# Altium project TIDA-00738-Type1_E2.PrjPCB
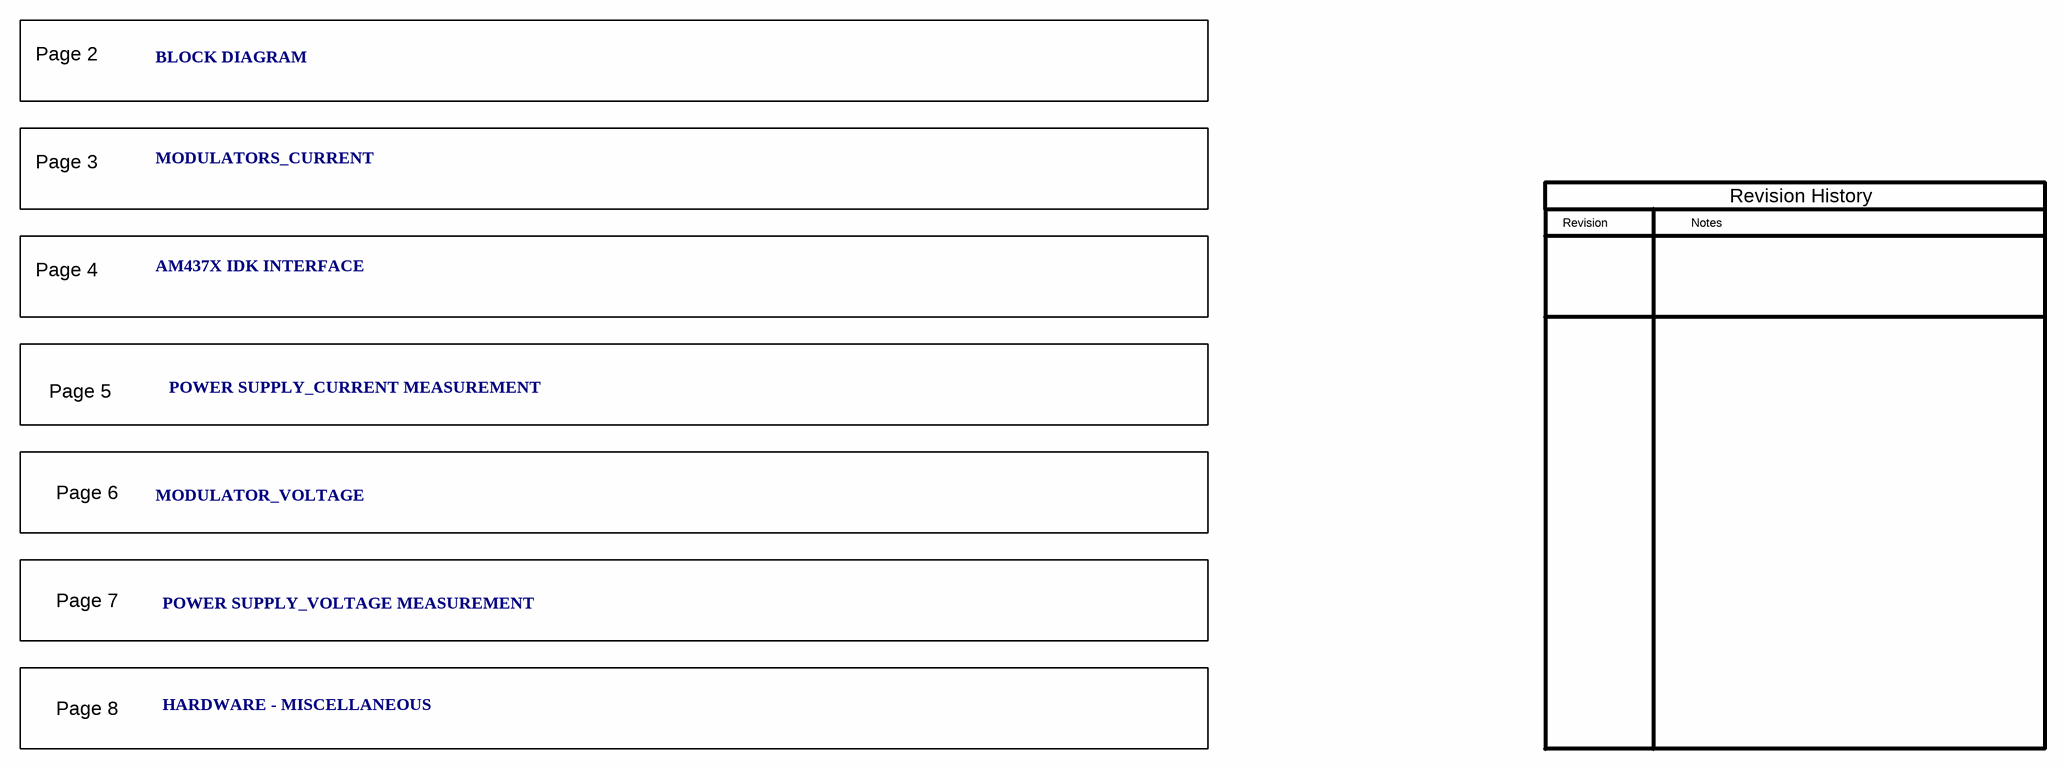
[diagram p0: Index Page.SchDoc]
CopyrightYear: 2013; PCB_Layout: Avinash; PCB_Rev: E2; PRJ_Customer: Public Release; PRJ_Engineer: Sunil Dwivedi; PRJ_Number: TIDA-00738; PRJ_Title: ICVM Using AMC1304 and SITARA Controller; SCH_Rev: E2; TechSupport: http://www.ti.com/support
8 sheets, 252 parts. Net scope: flat (ports and power ports of the same name join across sheets).
Board file: TIDA-00738-Type1_E2.PcbDoc
Sheets:
  Index Page.SchDoc
  Cover Sheet_ANSI-B.SchDoc
  Current Measurement.SchDoc
  Clock Generator.SchDoc
  Power Supply Current Measurment.SchDoc
  Voltage Measurment.SchDoc
  Power Supply Voltage Measurement.SchDoc
  Hardware_ANSI-B.SchDoc

## Sheet Index Page.SchDoc
size 431 x 279 mm; Date: Not shown in title block; ApprovedBy: Not shown in title block; CheckedBy: Not shown in title block; Author: Not shown in title block; CompanyName: Not shown in title block; Engineer: Not shown in title block; Organization: Not shown in title block; Address1: Not shown in title block; Address2: Not shown in title block; Address3: Not shown in title block; Address4: Not shown in title block; DocumentNumber: 1; Revision: Use project parameter SCH_Rev; SheetNumber: 1; SheetTotal: 8; PageSetup: Record=PageOptions¦CenterHorizontal=True¦CenterVertical=True¦PrintScale=1.00¦XCorrection=1.00¦YCorrection=1.00¦PrintKind=0¦BorderSize=5000000¦LeftOffset=0¦BottomOffset=0¦Orientation=2¦PaperLength=1000¦PaperWidth=1000¦Scale=100¦PaperSource=15¦PrintQuality=600¦MediaType=1¦DitherType=10¦PaperKind=Letter¦PrintScaleMode=1

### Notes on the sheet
- Page 2
- BLOCK DIAGRAM
- Page 3
- MODULATORS_CURRENT
- Revision
- Notes
- Revision History
- Page 4
- AM437X IDK INTERFACE
- Page 5
- POWER SUPPLY_CURRENT MEASUREMENT
- Page 6
- MODULATOR_VOLTAGE
- Page 7
- POWER SUPPLY_VOLTAGE MEASUREMENT
- Page 8
- HARDWARE - MISCELLANEOUS

## Sheet Cover Sheet_ANSI-B.SchDoc: Cover Sheet
size 431 x 279 mm; Date: Not shown in title block; ApprovedBy: Not shown in title block; CheckedBy: Not shown in title block; Author: Not shown in title block; CompanyName: Not shown in title block; Engineer: Not shown in title block; Organization: Not shown in title block; Address1: Not shown in title block; Address2: Not shown in title block; Address3: Not shown in title block; Address4: Not shown in title block; DocumentNumber: 1; Revision: Use project parameter SCH_Rev; SheetNumber: 2; SheetTotal: 8; PageSetup: Record=PageOptions¦CenterHorizontal=True¦CenterVertical=True¦PrintScale=1.00¦XCorrection=1.00¦YCorrection=1.00¦PrintKind=0¦BorderSize=5000000¦LeftOffset=0¦BottomOffset=0¦Orientation=2¦PaperLength=1000¦PaperWidth=1000¦Scale=100¦PaperSource=15¦PrintQuality=600¦MediaType=1¦DitherType=10¦PaperKind=Letter¦PrintScaleMode=1
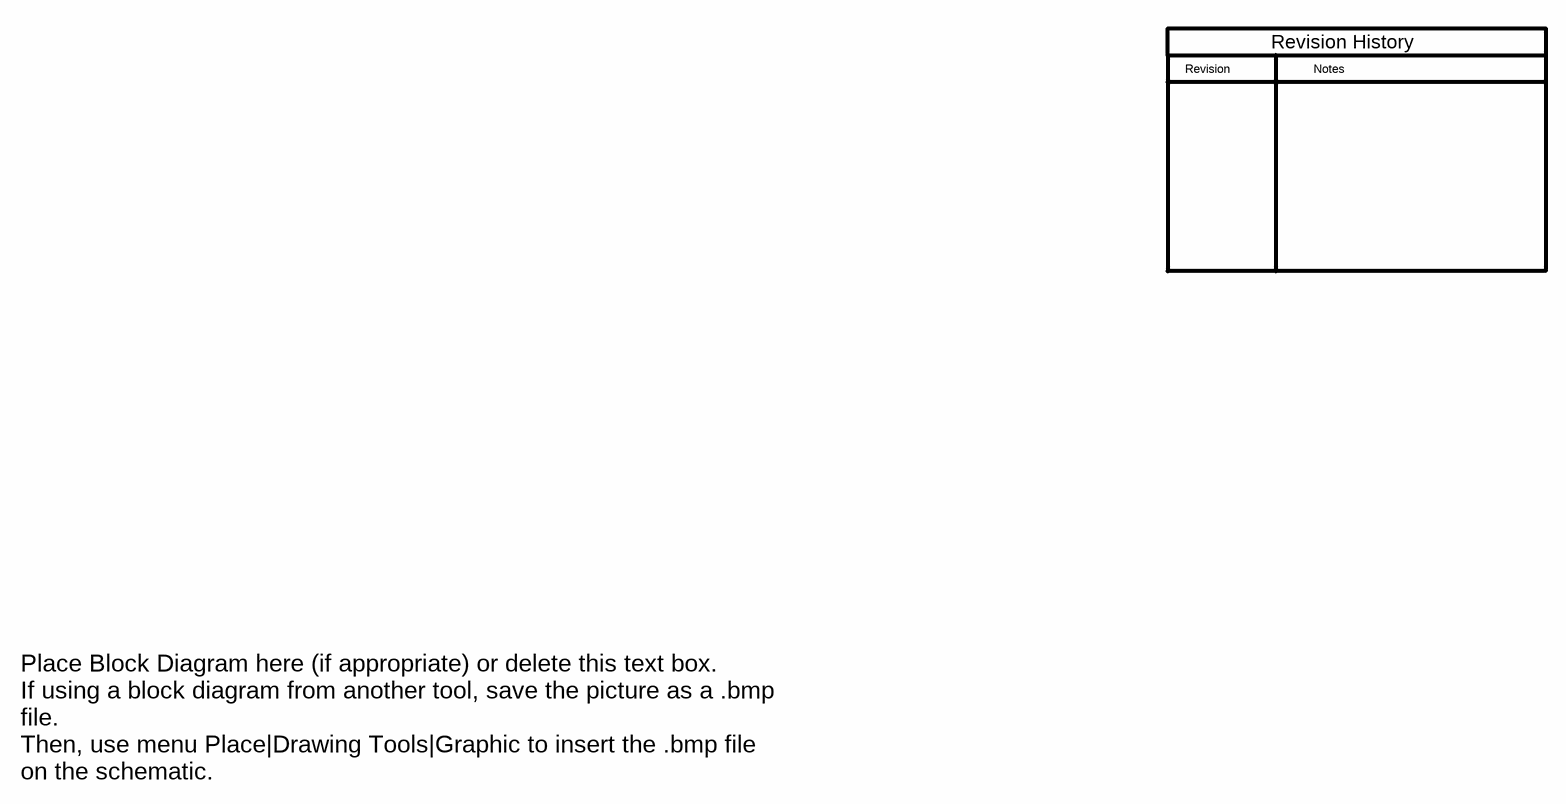
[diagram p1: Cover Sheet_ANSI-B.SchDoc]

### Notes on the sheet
- Revision
- Notes
- Revision History
- Place Block Diagram here (if appropriate) or delete this text box.
  If using a block diagram from another tool, save the picture as a .bmp file.
  Then, use menu Place|Drawing Tools|Graphic to insert the .bmp file on the schematic.

## Sheet Current Measurement.SchDoc: Current Measurement
size 431 x 279 mm; Date: Not shown in title block; ApprovedBy: Not shown in title block; CheckedBy: Not shown in title block; Author: Not shown in title block; CompanyName: Not shown in title block; Engineer: Not shown in title block; Organization: Not shown in title block; Address1: Not shown in title block; Address2: Not shown in title block; Address3: Not shown in title block; Address4: Not shown in title block; DocumentNumber: 1; Revision: Use project parameter SCH_Rev; SheetNumber: 3; SheetTotal: 8; PageSetup: Record=PageOptions¦CenterHorizontal=True¦CenterVertical=True¦PrintScale=1.00¦XCorrection=1.00¦YCorrection=1.00¦PrintKind=0¦BorderSize=5000000¦LeftOffset=0¦BottomOffset=0¦Orientation=2¦PaperLength=1000¦PaperWidth=1000¦Scale=100¦PaperSource=15¦PrintQuality=600¦MediaType=1¦DitherType=10¦PaperKind=Letter¦PrintScaleMode=1
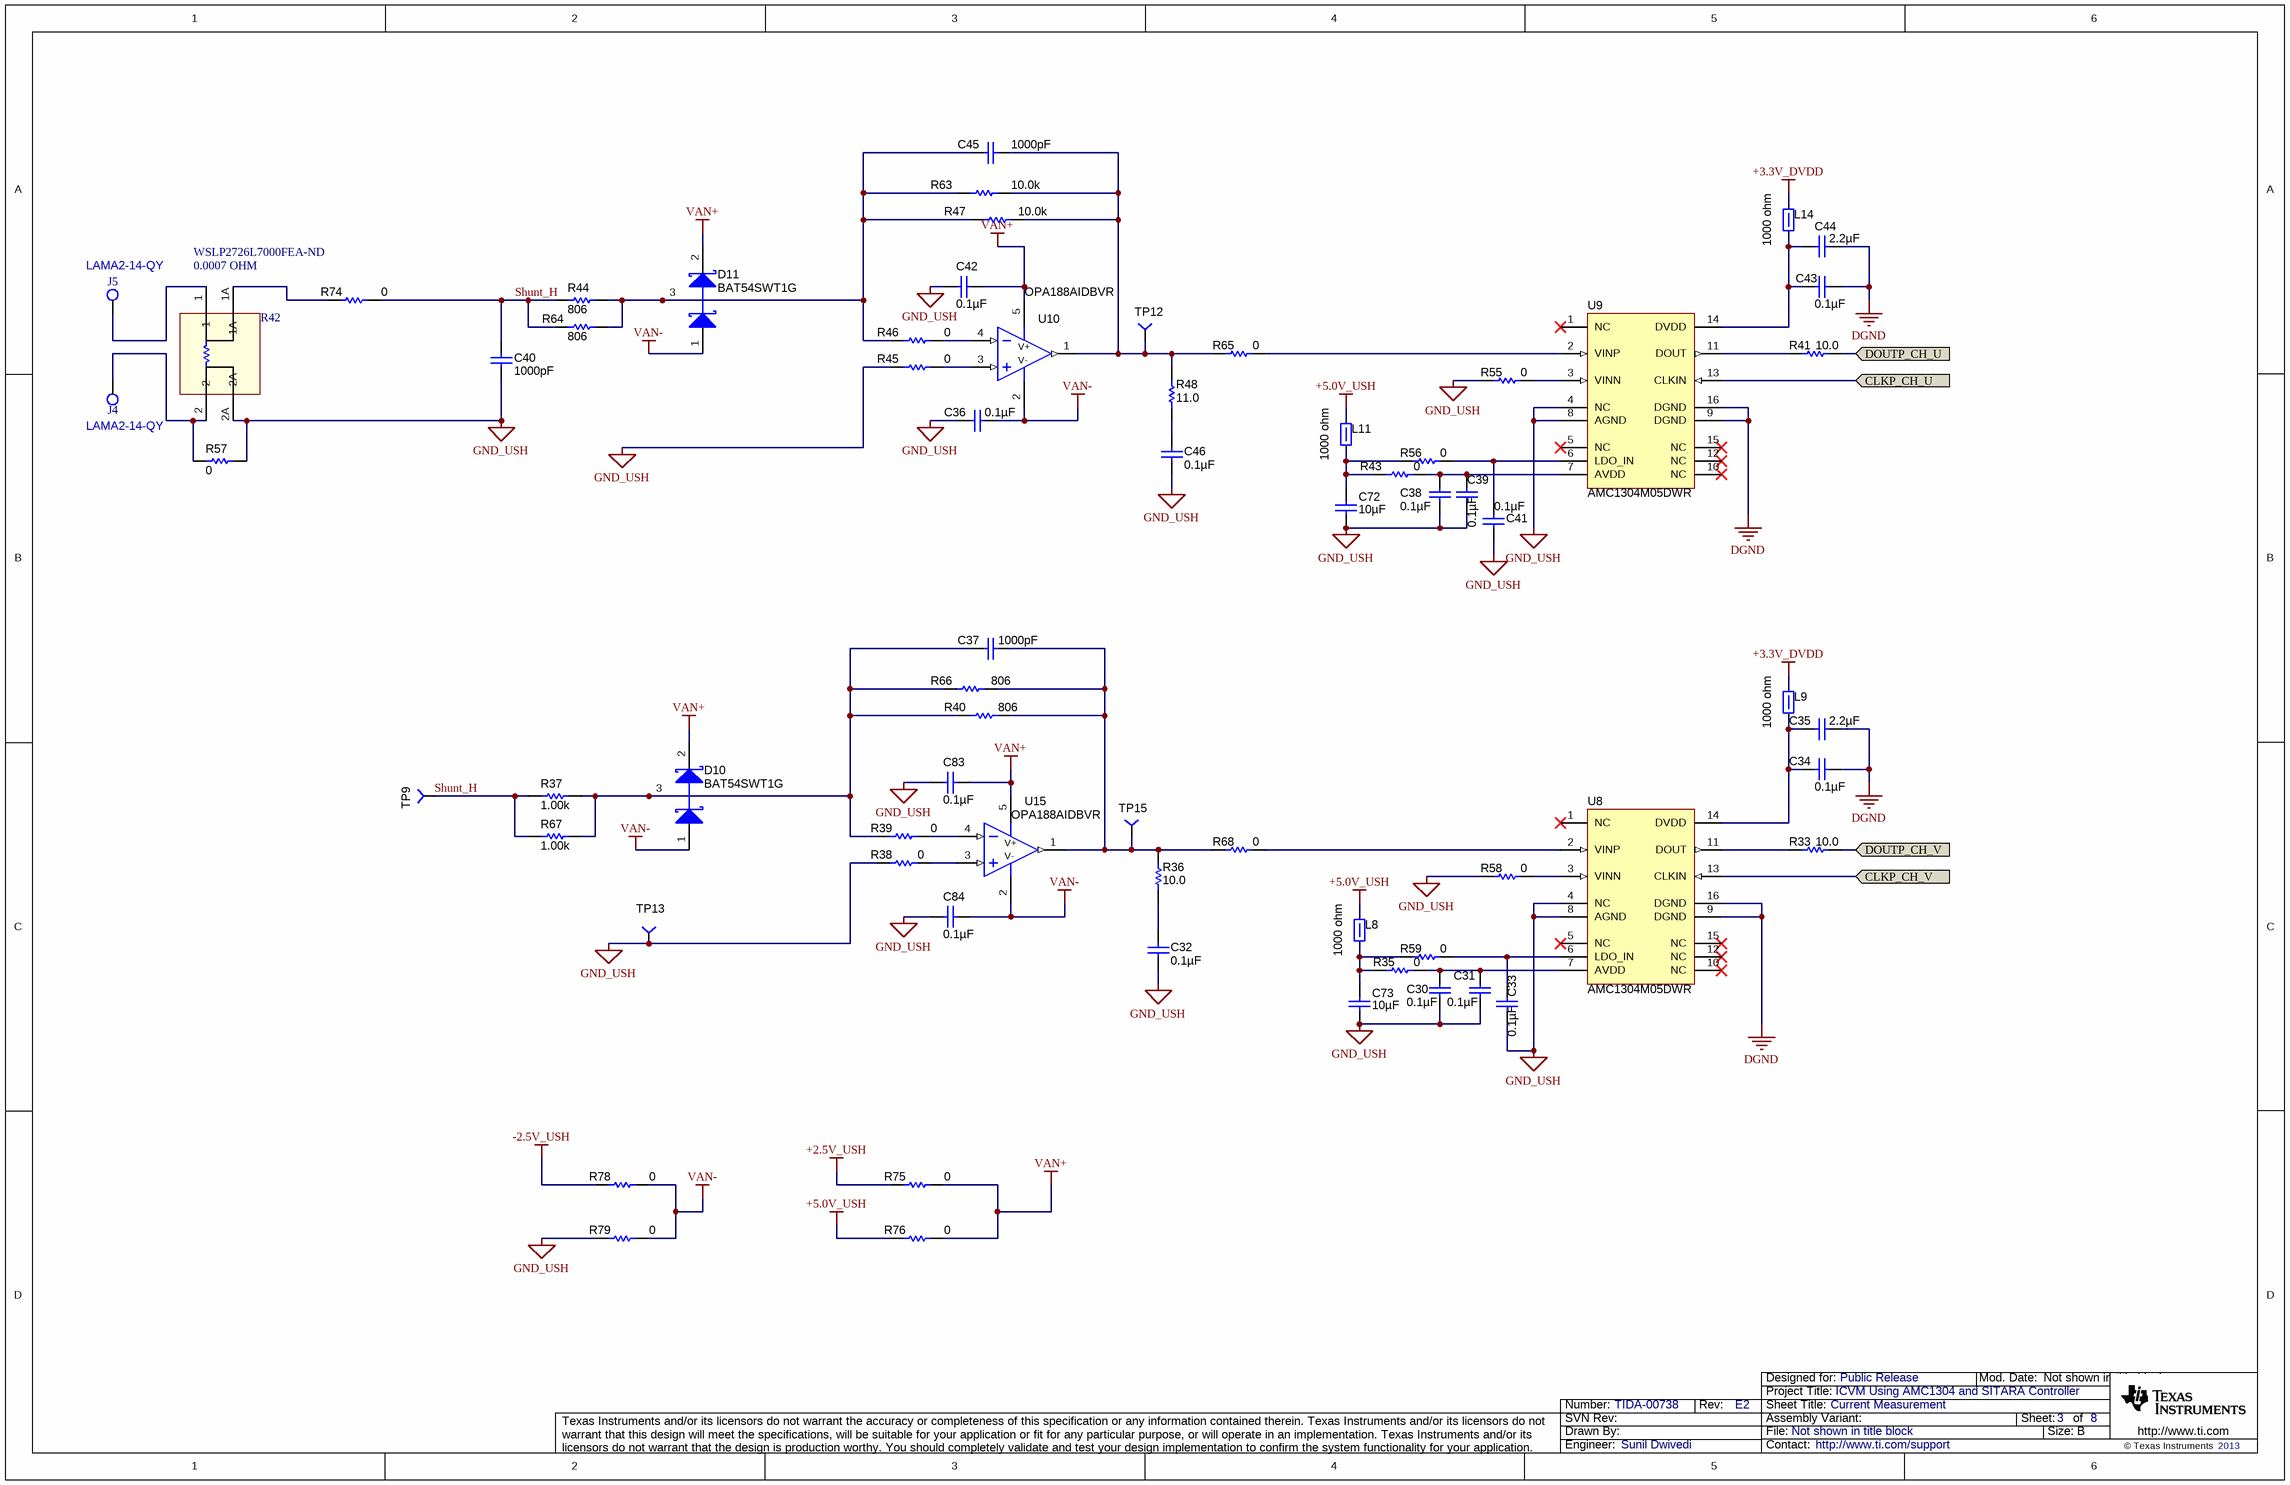
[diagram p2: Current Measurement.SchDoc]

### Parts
C30  ValueDisplayed: 0.1µF  [0603]
C31  ValueDisplayed: 0.1µF  [0603]
C32  ValueDisplayed: 0.1µF  [0603]  (hidden comment: GRM188R72A104KA35D)
C33  ValueDisplayed: 0.1µF  [0603]
C34  ValueDisplayed: 0.1µF  [0603]
C35  ValueDisplayed: 2.2µF  [0603]  (hidden comment: GRM188R71A225KE15D)
C36  ValueDisplayed: 0.1µF  [0603]
C37  ValueDisplayed: 1000pF  [0603]  (hidden comment: GRM1885C1H102FA01J)
C38  ValueDisplayed: 0.1µF  [0603]
C39  ValueDisplayed: 0.1µF  [0603]
C40  ValueDisplayed: 1000pF  [0603]  (hidden comment: GRM1885C1H102FA01J)
C41  ValueDisplayed: 0.1µF  [0603]
C42  ValueDisplayed: 0.1µF  [0603]
C43  ValueDisplayed: 0.1µF  [0603]
C44  ValueDisplayed: 2.2µF  [0603]  (hidden comment: GRM188R71A225KE15D)
C45  ValueDisplayed: 1000pF  [0603]  (hidden comment: GRM1885C1H102FA01J)
C46  ValueDisplayed: 0.1µF  [0603]  (hidden comment: GRM188R72A104KA35D)
C72  ValueDisplayed: 10µF  [1210]
C73  ValueDisplayed: 10µF  [1210]
C83  ValueDisplayed: 0.1µF  [0603]
C84  ValueDisplayed: 0.1µF  [0603]
D10  BAT54SWT1G  [SOT-323]
D11  BAT54SWT1G  [SOT-323]
J4  LAMA2-14-QY  [PANDUIT_LAMA2-14-QY]
J5  LAMA2-14-QY  [PANDUIT_LAMA2-14-QY]
L8  value 1000 ohm  [MMZ1608_095]  (hidden comment: MMZ1608B102CTA00)
L9  value 1000 ohm  [MMZ1608_095]  (hidden comment: MMZ1608B102CTA00)
L11  value 1000 ohm  [MMZ1608_095]  (hidden comment: MMZ1608B102CTA00)
L14  value 1000 ohm  [MMZ1608_095]  (hidden comment: MMZ1608B102CTA00)
R33  value 10.0  [0603]
R35  value 0  [0603]
R36  ValueDisplayed: 10.0  [0603]  (hidden comment: RC0603FR-0710RL)
R37  ValueDisplayed: 1.00k  [0603]  (hidden comment: CRCW06031K00FKEA)
R38  value 0  [0603]
R39  ValueDisplayed: 0  [0603]  (hidden comment: CRCW06030000Z0EA)
R40  ValueDisplayed: 806  [0603]  (hidden comment: CRCW0603806RFKEA)
R41  value 10.0  [0603]
R42  WSLP2726L7000FEA-ND  value 0.0007 OHM  [RES_WSLP2726]
R43  value 0  [0603]
R44  ValueDisplayed: 806  [0603]  (hidden comment: CRCW0603806RFKEA)
R45  value 0  [0603]
R46  ValueDisplayed: 0  [0603]  (hidden comment: CRCW06030000Z0EA)
R47  ValueDisplayed: 10.0k  [0603]  (hidden comment: RC0603FR-0710KL)
R48  ValueDisplayed: 11.0  [0603]  (hidden comment: RC0603FR-0711RL)
R55  value 0  [0603]
R56  value 0  [0603]
R57  ValueDisplayed: 0  [1206]  (hidden comment: CRCW12060000Z0EA)
R58  value 0  [0603]
R59  value 0  [0603]
R63  ValueDisplayed: 10.0k  [0603]  (hidden comment: RC0603FR-0710KL)
R64  ValueDisplayed: 806  [0603]  (hidden comment: CRCW0603806RFKEA)
R65  value 0  [0603]
R66  ValueDisplayed: 806  [0603]  (hidden comment: CRCW0603806RFKEA)
R67  ValueDisplayed: 1.00k  [0603]  (hidden comment: CRCW06031K00FKEA)
R68  value 0  [0603]
R74  value 0  [0603]
R75  value 0  [0603]
R76  value 0  [0603]
R78  value 0  [0603]
R79  value 0  [0603]
TP9  (no value)  [TP-040_RND]
TP12  (no value)  [TP-040_RND]
TP13  (no value)  [TP-040_RND]
TP15  (no value)  [TP-040_RND]
U8  AMC1304M05DWR  [DW0016B_N]
U9  AMC1304M05DWR  [DW0016B_N]
U10  OPA188AIDBVR  [DBV0005A_N]
U15  OPA188AIDBVR  [DBV0005A_N]

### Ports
CLKP_CH_U, CLKP_CH_V, DOUTP_CH_U, DOUTP_CH_V

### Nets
+2.5V_USH: R75.1
+3.3V_DVDD: L9.2 L14.2
+5.0V_USH: L8.2 L11.2 R76.1
-2.5V_USH: R78.1
DGND: C34.1 C35.1 C43.1 C44.1 U8.9(DGND) U8.16(DGND) U9.9(DGND) U9.16(DGND)
GND_USH: C30.2 C31.2 C32.2 C33.2 C36.1 C38.2 C39.2 C40.2 C41.2 C42.1 C46.2 C72.1 C73.1 C83.1 C84.1 R38.1 R42.2A R45.1 R55.1 R57.2 R58.1 R79.1 TP13.1 U8.4(NC) U8.8(AGND) U9.4(NC) U9.8(AGND)
VAN+: C42.2 C83.2 D10.2(K) D11.2(K) R75.2 R76.2 U10.5(V+) U15.5(V+)
VAN-: C36.2 C84.2 D10.1(A) D11.1(A) R78.2 R79.2 U10.2(V-) U15.2(V-)
CLKP_CH_U: U9.13(CLKIN) ; port CLKP_CH_U
CLKP_CH_V: U8.13(CLKIN) ; port CLKP_CH_V
DOUTP_CH_U: R41.2 ; port DOUTP_CH_U
DOUTP_CH_V: R33.2 ; port DOUTP_CH_V
Shunt_H: C40.1 R37.1 R44.1 R64.1 R67.1 R74.2 TP9.1
NetC30_1: C30.1 C31.1 R35.2 U8.7(AVDD)
NetC32_1: C32.1 R36.1
NetC33_1: C33.1 R59.2 U8.6(LDO_IN)
NetC34_2: C34.2 C35.2 L9.1 U8.14(DVDD)
NetC37_1: C37.1 R36.2 R40.2 R66.2 R68.1 TP15.1 U15.1(OUT)
NetC37_2: C37.2 D10.3(C) R37.2 R39.1 R40.1 R66.1 R67.2
NetC38_1: C38.1 C39.1 R43.2 U9.7(AVDD)
NetC41_1: C41.1 R56.2 U9.6(LDO_IN)
NetC43_2: C43.2 C44.2 L14.1 U9.14(DVDD)
NetC45_1: C45.1 R47.2 R48.2 R63.2 R65.1 TP12.1 U10.1(OUT)
NetC45_2: C45.2 D11.3(C) R44.2 R46.1 R47.1 R63.1 R64.2
NetC46_1: C46.1 R48.1
NetC72_2: C72.2 L11.1 R43.1 R56.1
NetC73_2: C73.2 L8.1 R35.1 R59.1
NetJ4_1: J4.1 R42.2 R57.1
NetJ5_1: J5.1 R42.1
NetR33_1: R33.1 U8.11(DOUT)
NetR38_2: R38.2 U15.3(IN+)
NetR39_2: R39.2 U15.4(IN-)
NetR41_1: R41.1 U9.11(DOUT)
NetR42_1A: R42.1A R74.1
NetR45_2: R45.2 U10.3(IN+)
NetR46_2: R46.2 U10.4(IN-)
NetR55_2: R55.2 U9.3(VINN)
NetR58_2: R58.2 U8.3(VINN)
NetR65_2: R65.2 U9.2(VINP)
NetR68_2: R68.2 U8.2(VINP)

Not connected (* = marked no-connect by the designer): U8 1(NC)* 5(NC)* 10(NC)* 12(NC)* 15(NC)*; U9 1(NC)* 5(NC)* 10(NC)* 12(NC)* 15(NC)*

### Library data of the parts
C30 C31 C33 C36 C38 C39 C41 C42 C83 C84 = C0603C104K5RACTU: CAP, CERM, 0.1uF, 50V, +/-10%, X7R, 0603; Manufacturer: Kemet; Polarized: N; CompType: Capacitor; U/M: EA; Cap_F: 0.0000001; Tolerance_%: 10; Value1: Unknown; VDC_V: 50; TaMin_C: -55; TaMax_C: 125
C32 C46 = GRM188R72A104KA35D: CAP, CERM, 0.1 µF, 100 V, +/- 10%, X7R, 0603; Manufacturer: MuRata; Polarized: N; CompType: Capacitor; Value: 0.1uF; U/M: EA; Cap_F: 0.0000001; Tolerance_%: 10; Value1: Unknown; VDC_V: 100; Value2: 100V; TaMin_C: -55; TaMax_C: 125; AEC Category: Q200
C34 C43 = 06033C104JAT2A: CAP, CERM, 0.1uF, 25V, +/-5%, X7R, 0603; Manufacturer: AVX; Polarized: N; CompType: Capacitor; U/M: EA; Cap_F: 0.0000001; Tolerance_%: 5; ESR_Ohm: 0.05; Value1: 0.05 ohm; VDC_V: 25; TaMin_C: -55; TaMax_C: 125
C35 C44 = GRM188R71A225KE15D: CAP, CERM, 2.2 µF, 10 V, +/- 10%, X7R, 0603; Manufacturer: MuRata; Polarized: N; CompType: Capacitor; Value: 2.2uF; U/M: EA; Cap_F: 0.0000022; Tolerance_%: 10; ESR_ohm: 0.009; Value1: 0.009 ohm; Value2: 10V; TaMin_C: -55; TaMax_C: 125; AEC Category: Q200
C37 C40 C45 = GRM1885C1H102FA01J: CAP, CERM, 1000 pF, 50 V, +/- 1%, C0G/NP0, 0603; Manufacturer: MuRata; Polarized: N; CompType: Capacitor; Value: 1000pF; U/M: EA; Cap_F: 0.000000001; Tolerance_%: 1; Value1: Unknown; VDC_V: 50; Value2: 50V; TaMin_C: -55; TaMax_C: 125; AEC Category: Q200
C72 C73 = GMK325AB7106MM-T: CAP, CERM, 10uF, 35V, +/-20%, X7R, 1210; Manufacturer: Taiyo Yuden; Polarized: N; CompType: Capacitor; U/M: EA; Cap_F: 0.00001; Tolerance_%: 20; Value1: Unknown; VDC_V: 35; TaMin_C: -55; TaMax_C: 125
D10 D11 = BAT54SWT1G: Diode, Schottky, 30 V, 0.2 A, SOT-323; Manufacturer: Fairchild Semiconductor; U/M: EA; Vf_V: 0.8; Value: 30V; Value1: 0.2A; Value2: 0.8V; Io_A: 0.2; Vr_V: 30; TJmax_C: 125; AEC Category: Q101
J4 J5 = LAMA2-14-QY: MECHANICAL LUG ALUM 2-14 AWG; Manufacturer: Panduit Corp
L8 L9 L11 L14 = MMZ1608B102CTA00: Ferrite Bead, 1000 ohm @ 100 MHz, 0.3 A, 0603; Manufacturer: TDK; Imax_A: 0.3; DCR_ohm: 0.6; Value1: 0.6 ohm; Value2: 0.3A; ZTyp@100MHz_Ohm: 1000
R33 R41 = CRCW060310R0FKEA: RES, 10.0 ohm, 1%, 0.1W, 0603; Manufacturer: Vishay-Dale; CompType: Resistor; Res_ohm: 10; Value_Code: 10R0; Tolerance_%: 1; Power_W: 0.1; VDC_V: 75; TempCo: 100 ppm/C; EIA_Code: E96; U/M: EA
R35 R38 R43 R45 R55 R56 R58 R59 R65 R68 R74-R76 R78 R79 = CRCW06030000Z0EA: RES, 0 ohm, 5%, 0.1W, 0603; Manufacturer: Vishay-Dale; CompType: Resistor; Value_Code: 0000; Tolerance_%: 5; Power_W: 0.1; VDC_V: 75; TempCo: 200 ppm/C; EIA_Code: E24; U/M: EA
R36 = RC0603FR-0710RL: RES, 10.0, 1%, 0.1 W, 0603; Manufacturer: Yageo America; CompType: Resistor; Value: 10.0; Res_ohm: 10; Value_Code: 10R0; Tolerance_%: 1; Power_W: 0.1; Value2: 0.1W; VDC_V: 150; TempCo: 200 ppm/C; EIA_Code: E96; U/M: EA; AEC Category: Q200
R37 R67 = CRCW06031K00FKEA: RES, 1.00 k, 1%, 0.1 W, 0603; Manufacturer: Vishay-Dale; CompType: Resistor; Value: 1.00k; Res_ohm: 1000; Value_Code: 1k00; Tolerance_%: 1; Power_W: 0.1; Value2: 0.1W; VDC_V: 75; TempCo: 100 ppm/C; EIA_Code: E96; U/M: EA; AEC Category: Q200
R39 R46 = CRCW06030000Z0EA: RES, 0, 5%, 0.1 W, 0603; Manufacturer: Vishay-Dale; CompType: Resistor; Value: 0; Value_Code: 0000; Tolerance_%: 5; Power_W: 0.1; Value2: 0.1W; VDC_V: 75; TempCo: 200 ppm/C; EIA_Code: E24; U/M: EA; AEC Category: Q200
R40 R44 R64 R66 = CRCW0603806RFKEA: RES, 806, 1%, 0.1 W, 0603; Manufacturer: Vishay-Dale; CompType: Resistor; Value: 806; Value_Code: 806R; Tolerance_%: 1; Power_W: 0.1; Value2: 0.1W; VDC_V: 75; TempCo: 100 ppm/C; EIA_Code: E96; U/M: EA; AEC Category: Q200
R42 = WSLP2726L5000FEA: RES SMD 0.0007 OHM 1% 7W 2726; Manufacturer: VISHAY; CompType: RESISTOR; SymbolCreator: x0199378
R47 R63 = RC0603FR-0710KL: RES, 10.0 k, 1%, 0.1 W, 0603; Manufacturer: Yageo America; CompType: Resistor; Value: 10.0k; Res_ohm: 10000; Value_Code: 10k0; Tolerance_%: 1; Power_W: 0.1; Value2: 0.1W; VDC_V: 150; TempCo: 200 ppm/C; EIA_Code: E96; U/M: EA; AEC Category: Q200
R48 = RC0603FR-0711RL: RES, 11.0, 1%, 0.1 W, 0603; Manufacturer: Yageo America; CompType: Resistor; Value: 11.0; Res_ohm: 11; Value_Code: 11R0; Tolerance_%: 1; Power_W: 0.1; Value2: 0.1W; VDC_V: 150; TempCo: 200 ppm/C; EIA_Code: E96; U/M: EA; AEC Category: Q200
R57 = CRCW12060000Z0EA: RES, 0, 5%, 0.25 W, 1206; Manufacturer: Vishay-Dale; CompType: Resistor; Value: 0; Value_Code: 0000; Tolerance_%: 5; Power_W: 0.25; Value2: 0.25W; VDC_V: 200; TempCo: 200 ppm/C; EIA_Code: E24; U/M: EA
TP9 TP12 TP13 TP15 = TP-040_RND: Test Point, O.040 Hole; Manufacturer: STD; Value: STD
U8 U9 = AMC1304M25DW: High-Precision, Reinforced Isolated Delta-Sigma Modulators with LDO, DW0016B; Manufacturer: Texas Instruments; SymbolCreator: a0411947; CompType: IC; U/M: EA
U10 U15 = OPA188AIDBVR: Precision, Low-Noise, Rail-to-Rail Output, 36 V, Zero-Drift Operational Amplifiers, DBV0005A; Alternate PartNumber: OPA188AIDBVT; Manufacturer: Texas Instruments; CompType: IC; U/M: EA

## Sheet Clock Generator.SchDoc: Clock Generator
size 431 x 279 mm; Date: Not shown in title block; ApprovedBy: Not shown in title block; CheckedBy: Not shown in title block; Author: Not shown in title block; CompanyName: Not shown in title block; Engineer: Not shown in title block; Organization: Not shown in title block; Address1: Not shown in title block; Address2: Not shown in title block; Address3: Not shown in title block; Address4: Not shown in title block; DocumentNumber: 1; Revision: Use project parameter SCH_Rev; SheetNumber: 4; SheetTotal: 8; PageSetup: Record=PageOptions¦CenterHorizontal=True¦CenterVertical=True¦PrintScale=1.00¦XCorrection=1.00¦YCorrection=1.00¦PrintKind=0¦BorderSize=5000000¦LeftOffset=0¦BottomOffset=0¦Orientation=2¦PaperLength=1000¦PaperWidth=1000¦Scale=100¦PaperSource=15¦PrintQuality=600¦MediaType=1¦DitherType=10¦PaperKind=Letter¦PrintScaleMode=1
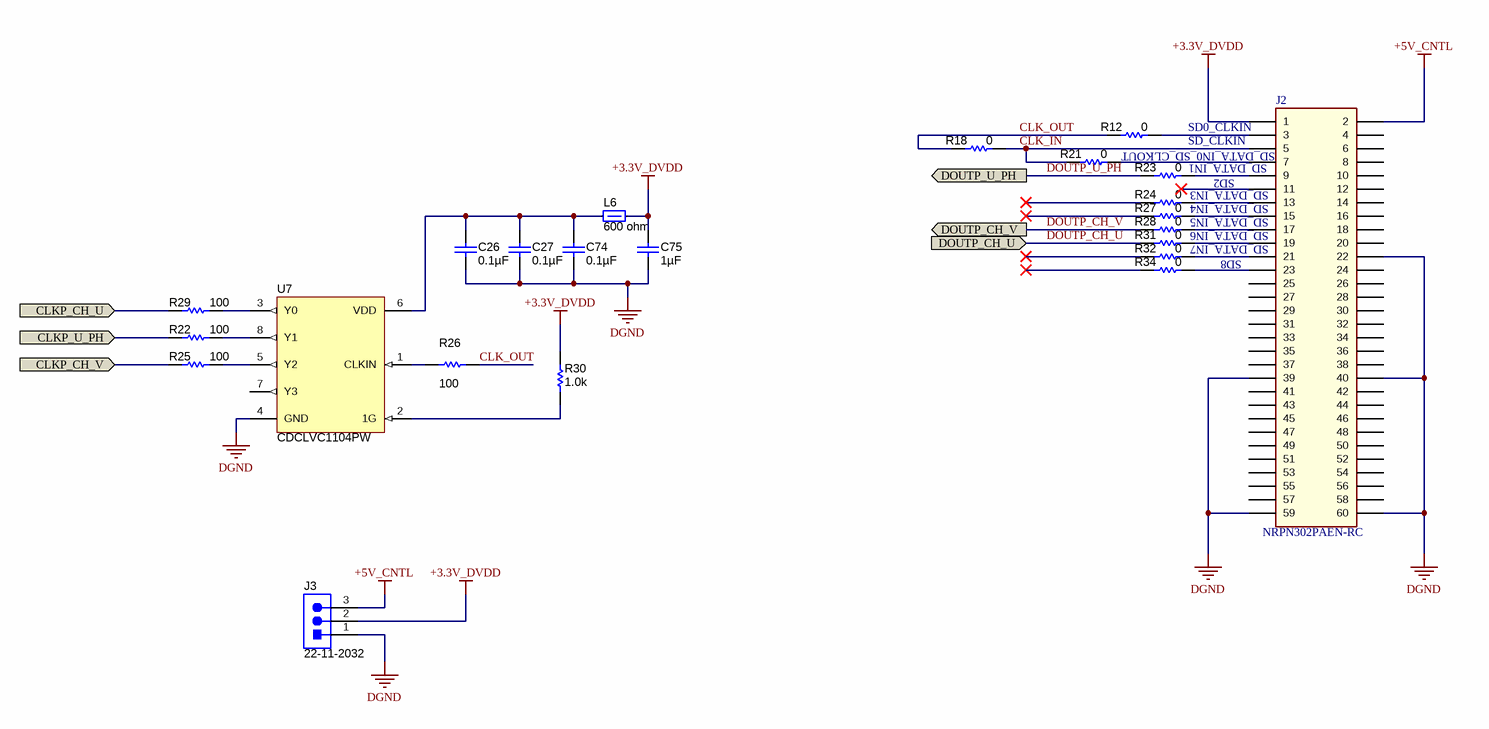
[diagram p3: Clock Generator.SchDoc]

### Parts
C26  ValueDisplayed: 0.1µF  [0603]  (hidden comment: 06033C104JAT2A)
C27  ValueDisplayed: 0.1µF  [0603]  (hidden comment: 06033C104JAT2A)
C74  ValueDisplayed: 0.1µF  [0603]  (hidden comment: 06033C104JAT2A)
C75  ValueDisplayed: 1µF  [0603]  (hidden comment: GRM188R71A105KA61D)
J2  NRPN302PAEN-RC  [CONN_NRPN302PAEN-RC]
J3  22-11-2032  [Molex_22-11-2032]
L6  value 600 ohm  [0603]  (hidden comment: BLM18KG601SN1D)
R12  value 0  [0603]  (hidden comment: CRCW06030000Z0EA)
R18  value 0  [0603]  (hidden comment: CRCW06030000Z0EA)
R21  value 0  [0603]  (hidden comment: CRCW06030000Z0EA)
R22  ValueDisplayed: 100  [0603]  (hidden comment: CRCW0603100RFKEA)
R23  value 0  [0603]  (hidden comment: CRCW06030000Z0EA)
R24  value 0  [0603]  (hidden comment: CRCW06030000Z0EA)
R25  ValueDisplayed: 100  [0603]  (hidden comment: CRCW0603100RFKEA)
R26  ValueDisplayed: 100  [0603]  (hidden comment: CRCW0603100RFKEA)
R27  value 0  [0603]  (hidden comment: CRCW06030000Z0EA)
R28  value 0  [0603]  (hidden comment: CRCW06030000Z0EA)
R29  ValueDisplayed: 100  [0603]  (hidden comment: CRCW0603100RFKEA)
R30  value 1.0k  [0603]  (hidden comment: CRCW06031K00JNEA)
R31  value 0  [0603]  (hidden comment: CRCW06030000Z0EA)
R32  value 0  [0603]  (hidden comment: CRCW06030000Z0EA)
R34  value 0  [0603]  (hidden comment: CRCW06030000Z0EA)
U7  CDCLVC1104PW  [PW0008A_N]

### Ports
CLKP_CH_U, CLKP_CH_V, CLKP_U_PH (in), DOUTP_CH_U, DOUTP_CH_V, DOUTP_U_PH (out)

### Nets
+3.3V_DVDD: C75.1 J2.1 J3.2 L6.1 R30.2
+5V_CNTL: J2.2 J3.3
DGND: C26.2 C27.2 C74.2 C75.2 J2.22 J2.39 J2.40 J2.59 J2.60 J3.1 U7.4(GND)
CLK_IN: J2.5 R18.2 R21.1
CLK_OUT: R12.1 R18.1 R26.2
CLKP_CH_U: R29.1 ; port CLKP_CH_U
CLKP_CH_V: R25.1 ; port CLKP_CH_V
CLKP_U_PH: R22.1 ; port CLKP_U_PH
DOUTP_CH_U: R31.1 ; port DOUTP_CH_U
DOUTP_CH_V: R28.1 ; port DOUTP_CH_V
DOUTP_U_PH: R23.1 ; port DOUTP_U_PH
NetC26_1: C26.1 C27.1 C74.1 L6.2 U7.6(VDD)
NetJ2_3: J2.3 R12.2
NetJ2_7: J2.7 R21.2
NetJ2_9: J2.9 R23.2
NetJ2_13: J2.13 R24.2
NetJ2_15: J2.15 R27.2
NetJ2_17: J2.17 R28.2
NetJ2_19: J2.19 R31.2
NetJ2_21: J2.21 R32.2
NetJ2_23: J2.23 R34.2
NetR22_2: R22.2 U7.8(Y1)
NetR25_2: R25.2 U7.5(Y2)
NetR26_1: R26.1 U7.1(CLKIN)
NetR29_2: R29.2 U7.3(Y0)
NetR30_1: R30.1 U7.2(1G)

Not connected (* = marked no-connect by the designer): J2 4 6 8 10 11* 12 14 16 18 20 24 25 26 27 28 29 30 31 32 33 34 35 36 37 38 41 42 43 44 45 46 47 48 49 50 51 52 53 54 55 56 57 58; R24 1*; R27 1*; R32 1*; R34 1*; U7 7(Y3)

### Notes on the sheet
- SD_CLKIN
- SD0_CLKIN
- (near J2) SD_DATA_IN0_SD_CLKOUT
- SD2
- (near J2) SD_DATA_IN1
- (near J2) SD_DATA_IN3
- (near J2) SD_DATA_IN4
- (near J2) SD_DATA_IN5
- SD8
- (near J2) SD_DATA_IN6
- (near J2) SD_DATA_IN7

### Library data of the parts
C26 C27 C74 = 06033C104JAT2A: as C34 on sheet Current Measurement
C75 = GRM188R71A105KA61D: CAP, CERM, 1uF, 10V, +/-10%, X7R, 0603; Manufacturer: MuRata; Polarized: N; CompType: Capacitor; U/M: EA; Cap_F: 0.000001; Tolerance_%: 10; ESR_Ohm: 0.011; Value1: 0.011 ohm; TaMin_C: -55; TaMax_C: 125
J2 = CON-NRPN302PAEN-RC: CONN HEADER 2MM DUAL STR 60POS; Manufacturer: Sullins Connector Solutions; CompType: Connector
J3 = 22-11-2032: Header, 2.54 mm, 3x1, TH; Manufacturer: Molex; SymbolCreator: a0799628; U/M: EA
L6 = BLM18KG601SN1D: Ferrite Bead, 600 ohm @ 100MHz, 1.3A, 0603; Manufacturer: MuRata; Imax_A: 1.3; DCR_ohm: 0.15; Value1: 0.15 ohm; ZTyp@100MHz_Ohm: 600
R12 R18 R21 R23 R24 R27 R28 R31 R32 R34 = CRCW06030000Z0EA: as R35 on sheet Current Measurement
R22 R25 R26 R29 = CRCW0603100RFKEA: RES, 100, 1%, 0.1 W, 0603; Manufacturer: Vishay-Dale; CompType: Resistor; Value: 100; Value_Code: 100R; Tolerance_%: 1; Power_W: 0.1; Value2: 0.1W; VDC_V: 75; TempCo: 100 ppm/C; EIA_Code: E96; U/M: EA
R30 = CRCW06031K00JNEA: RES, 1.0k ohm, 5%, 0.1W, 0603; Manufacturer: Vishay-Dale; CompType: Resistor; Res_ohm: 1000; Value_Code: 1k00; Tolerance_%: 5; Power_W: 0.1; VDC_V: 75; TempCo: 200 ppm/C; EIA_Code: E24; U/M: EA
U7 = CDCLVC1104PW: 3.3 V and 2.5 V LVCMOS High-Performance Clock Buffer; Manufacturer: Texas Instruments; SymbolCreator: a0411947; CompType: IC; U/M: EA

## Sheet Power Supply Current Measurment.SchDoc: Power Supply Current Measurement
size 431 x 279 mm; Date: Not shown in title block; ApprovedBy: Not shown in title block; CheckedBy: Not shown in title block; Author: Not shown in title block; CompanyName: Not shown in title block; Engineer: Not shown in title block; Organization: Not shown in title block; Address1: Not shown in title block; Address2: Not shown in title block; Address3: Not shown in title block; Address4: Not shown in title block; DocumentNumber: 1; Revision: Use project parameter SCH_Rev; SheetNumber: 5; SheetTotal: 8; PageSetup: Record=PageOptions¦CenterHorizontal=True¦CenterVertical=True¦PrintScale=1.00¦XCorrection=1.00¦YCorrection=1.00¦PrintKind=0¦BorderSize=5000000¦LeftOffset=0¦BottomOffset=0¦Orientation=2¦PaperLength=1000¦PaperWidth=1000¦Scale=100¦PaperSource=15¦PrintQuality=600¦MediaType=1¦DitherType=10¦PaperKind=Letter¦PrintScaleMode=1
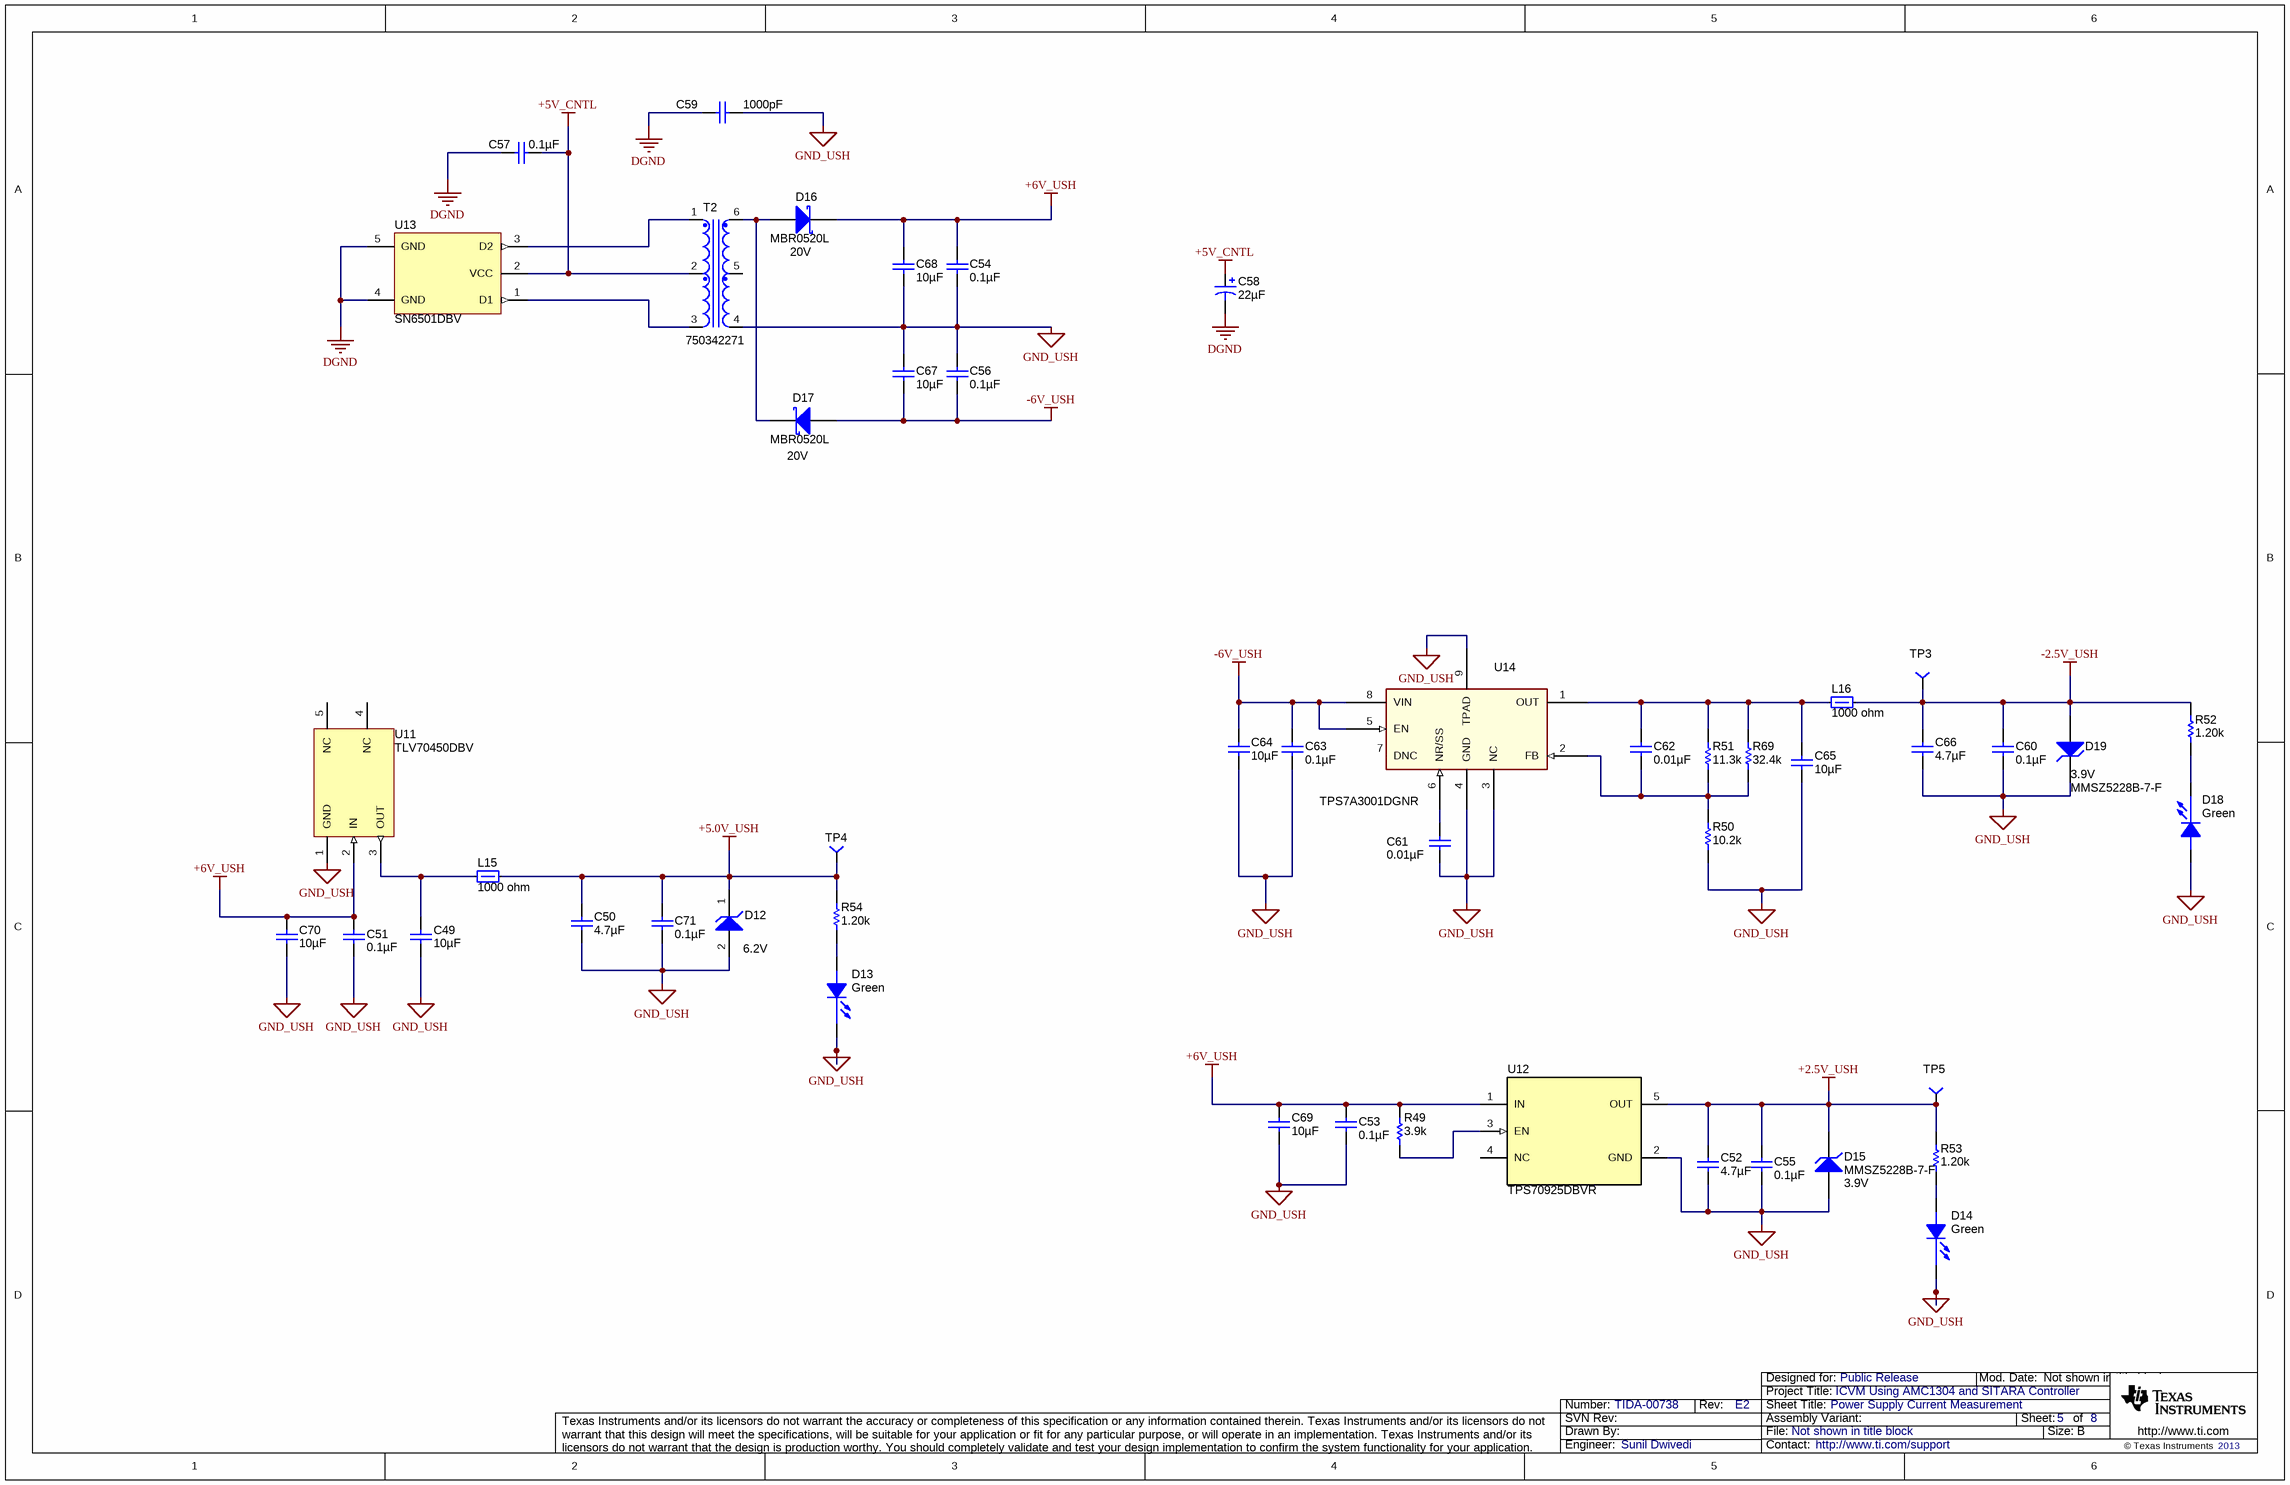
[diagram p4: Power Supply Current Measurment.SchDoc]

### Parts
C49  ValueDisplayed: 10µF  [1210]
C50  ValueDisplayed: 4.7µF  [0805_HV]
C51  ValueDisplayed: 0.1µF  [0603]
C52  ValueDisplayed: 4.7µF  [0805_HV]
C53  ValueDisplayed: 0.1µF  [0603]
C54  ValueDisplayed: 0.1µF  [0603]
C55  ValueDisplayed: 0.1µF  [0603]
C56  ValueDisplayed: 0.1µF  [0603]
C57  ValueDisplayed: 0.1µF  [0603]
C58  ValueDisplayed: 22µF  [SM_RADIAL_5MM]  (hidden comment: UUD1E220MCL1GS)
C59  value 1000pF  [CAP_200mil]
C60  ValueDisplayed: 0.1µF  [0603]
C61  ValueDisplayed: 0.01µF  [0603]
C62  ValueDisplayed: 0.01µF  [0603]
C63  ValueDisplayed: 0.1µF  [0603]
C64  ValueDisplayed: 10µF  [1210]
C65  ValueDisplayed: 10µF  [1210]
C66  ValueDisplayed: 4.7µF  [0805_HV]
C67  ValueDisplayed: 10µF  [1210]
C68  ValueDisplayed: 10µF  [1210]
C69  ValueDisplayed: 10µF  [1210]
C70  ValueDisplayed: 10µF  [1210]
C71  ValueDisplayed: 0.1µF  [0603]
D12  value 6.2V  [powerDI123]
D13  value Green  [LED0603AA]
D14  value Green  [LED0603AA]
D15  MMSZ5228B-7-F  value 3.9V  [SOD-123]
D16  MBR0520L  value 20V  [SOD-123]
D17  MBR0520L  value 20V  [SOD-123]
D18  value Green  [LED0603AA]
D19  MMSZ5228B-7-F  value 3.9V  [SOD-123]
L15  value 1000 ohm  [MMZ1608_095]  (hidden comment: MMZ1608B102CTA00)
L16  value 1000 ohm  [MMZ1608_095]  (hidden comment: MMZ1608B102CTA00)
R49  value 3.9k  [0603]
R50  ValueDisplayed: 10.2k  [0603]  (hidden comment: CRCW060310K2FKEA)
R51  ValueDisplayed: 11.3k  [0603]  (hidden comment: CRCW060311K3FKEA)
R52  ValueDisplayed: 1.20k  [0603]  (hidden comment: RC0603FR-071K2L)
R53  ValueDisplayed: 1.20k  [0603]  (hidden comment: RC0603FR-071K2L)
R54  ValueDisplayed: 1.20k  [0603]  (hidden comment: RC0603FR-071K2L)
R69  ValueDisplayed: 32.4k  [0603]  (hidden comment: CRCW060332K4FKEA)
T2  750342271  [760390015]
TP3  (no value)  [TP-040_RND]
TP4  (no value)  [TP-040_RND]
TP5  (no value)  [TP-040_RND]
U11  TLV70450DBV  [DBV0005A_N]
U12  TPS70925DBVR  [DBV0005A_N]
U13  SN6501DBV  [DBV0005A_N]
U14  TPS7A3001DGNR  [DGN0008D_N]

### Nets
+2.5V_USH: C52.2 C55.1 D15.1(K) R53.2 TP5.1 U12.5(OUT)
+5.0V_USH: C50.2 C71.1 D12.1(K) L15.2 R54.2 TP4.1
+5V_CNTL: C57.2 C58.1(+) T2.2 U13.2(VCC)
+6V_USH: C51.1 C53.1 C54.1 C68.1 C69.2 C70.2 D16.1(K) R49.2 U11.2(IN) U12.1(IN)
-2.5V_USH: C60.1 C66.2 D19.2(A) L16.2 R52.2 TP3.1
-6V_USH: C56.2 C63.1 C64.2 C67.2 D17.2(A) U14.5(EN) U14.8(VIN)
DGND: C57.1 C58.2(-) C59.1 U13.4(GND) U13.5(GND)
GND_USH: C49.1 C50.1 C51.2 C52.1 C53.2 C54.2 C55.2 C56.1 C59.2 C60.2 C61.1 C63.2 C64.1 C65.1 C66.1 C67.1 C68.2 C69.1 C70.1 C71.2 D12.2(A) D13.1(C) D14.1(C) D15.2(A) D18.2(A) D19.1(K) R50.1 T2.4 U11.1(GND) U12.2(GND) U14.3(NC) U14.4(GND) U14.9(TPAD)
NetC49_2: C49.2 L15.1 U11.3(OUT)
NetC61_2: C61.2 U14.6(NR/SS)
NetC62_1: C62.1 R50.2 R51.1 R69.1 U14.2(FB)
NetC62_2: C62.2 C65.2 L16.1 R51.2 R69.2 U14.1(OUT)
NetD13_2: D13.2(A) R54.1
NetD14_2: D14.2(A) R53.1
NetD16_2: D16.2(A) D17.1(K) T2.6
NetD18_1: D18.1(C) R52.1
NetR49_1: R49.1 U12.3(EN)
NetT2_1: T2.1 U13.3(D2)
NetT2_3: T2.3 U13.1(D1)

Not connected (* = marked no-connect by the designer): T2 5; U11 4(NC) 5(NC); U12 4(NC); U14 7(DNC)

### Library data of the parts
C49 C64 C65 C67-C70 = GMK325AB7106MM-T: as C72 on sheet Current Measurement
C50 C52 C66 = C2012X5R1H475K125AB: CAP, CERM, 4.7uF, 50V, +/-10%, X5R, 0805; Manufacturer: TDK; Polarized: N; CompType: Capacitor; U/M: EA; Cap_F: 0.0000047; Tolerance_%: 10; Value1: Unknown; VDC_V: 50; TaMin_C: -55; TaMax_C: 85; Cap_Case: 0805
C51 C53-C57 C60 C63 C71 = C0603C104K5RACTU: as C30 on sheet Current Measurement
C58 = UUD1E220MCL1GS: CAP, AL, 22uF, 25V, +/-20%, 0.76 ohm, SMD; Manufacturer: Nichicon; Polarized: Y; CompType: Capacitor; U/M: EA; Cap_F: 0.000022; Tolerance_%: 20; VDC_V: 25; ESR_Ohm: 0.76; IRMS_A: 0.15; TaMin_C: -55; TaMax_C: 105; Cap_Case: 5x5.8
C59 = 202R18W102KV4E: CAP CER 1000PF 1KV 10% RADIAL; PartNumber: S102K29Y5PN63J5R; Manufacturer: Vishay BC Components; Polarized: N; CompType: Capacitor; Tolerance_%: 0
C61 C62 = 06031C103JAT2A: CAP, CERM, 0.01uF, 100V, +/-5%, X7R, 0603; PartNumber: 06031C103J4Z4A; Manufacturer: AVX; Polarized: N; CompType: Capacitor; U/M: EA; Cap_F: 0.00000001; Tolerance_%: 5; ESR_Ohm: 0.098; Value1: 0.098 ohm; VDC_V: 100; TaMin_C: -55; TaMax_C: 125
D12 = DFLZ6V2-7: Diode, Zener, 6.2V, 1W, PowerDI123; Manufacturer: Diodes Inc.; U/M: EA; Power_W: 1; Vz_V: 6.2; RJA_CperW: 110
D13 D14 D18 = LED_LG L29K-G2J1-24-Z: LED SmartLED Green 570NM; Manufacturer: OSRAM; SymbolCreator: x0120606
D15 D19 = MMSZ5228B-7-F: Diode, Zener, 3.9 V, 500 mW, SOD-123; Manufacturer: Diodes Inc.; SymbolCreator: a0412235; U/M: EA; Power_W: 0.5; Vz_V: 3.9; Value1: 0.5W; RJA_CperW: 350; AEC Category: AEC-Q101
D16 D17 = MBR0520LT1G: Diode, Schottky, 20V, 0.5A, SOD-123; Manufacturer: Fairchild Semiconductor; U/M: EA; Vf_V: 0.385; Value2: 0.385V; Io_A: 0.5; Vr_V: 20; TJmax_C: 125; RJC_CperW: 150
L15 L16 = MMZ1608B102CTA00: as L8 on sheet Current Measurement
R49 = CRCW06033K90JNEA: RES, 3.9k ohm, 5%, 0.1W, 0603; Manufacturer: Vishay-Dale; CompType: Resistor; Res_ohm: 3900; Value_Code: 3k90; Tolerance_%: 5; Power_W: 0.1; VDC_V: 75; TempCo: 200 ppm/C; EIA_Code: E24; U/M: EA
R50 = CRCW060310K2FKEA: RES, 10.2 k, 1%, 0.1 W, 0603; Manufacturer: Vishay-Dale; CompType: Resistor; Value: 10.2k; Res_ohm: 10200; Value_Code: 10k2; Tolerance_%: 1; Power_W: 0.1; Value2: 0.1W; VDC_V: 75; TempCo: 100 ppm/C; EIA_Code: E96; U/M: EA
R51 = CRCW060311K3FKEA: RES, 11.3 k, 1%, 0.1 W, 0603; Manufacturer: Vishay-Dale; CompType: Resistor; Value: 11.3k; Res_ohm: 11300; Value_Code: 11k3; Tolerance_%: 1; Power_W: 0.1; Value2: 0.1W; VDC_V: 75; TempCo: 100 ppm/C; EIA_Code: E96; U/M: EA
R52-R54 = RC0603FR-071K2L: RES, 1.20 k, 1%, 0.1 W, 0603; Manufacturer: Yageo America; CompType: Resistor; Value: 1.20k; Res_ohm: 1200; Value_Code: 1k20; Tolerance_%: 1; Power_W: 0.1; Value2: 0.1W; VDC_V: 150; TempCo: 200 ppm/C; U/M: EA; AEC Category: Q200
R69 = CRCW060332K4FKEA: RES, 32.4 k, 1%, 0.1 W, 0603; Manufacturer: Vishay-Dale; CompType: Resistor; Value: 32.4k; Res_ohm: 32400; Value_Code: 32k4; Tolerance_%: 1; Power_W: 0.1; Value2: 0.1W; VDC_V: 75; TempCo: 100 ppm/C; EIA_Code: E96; U/M: EA; AEC Category: Q200
T2 = TRNSFMR: Transformer 469uH SMD; Manufacturer: Wurth Electronics Midcom
TP3-TP5 = TP-040_RND: as TP9 on sheet Current Measurement
U11 = TLV70450DBV: Regulator, LDO, 5V, 0.15A, SOT23-5; Alternate Manufacturer: None; Manufacturer: Texas Instruments; SymbolCreator: x0120606; CompType: IC
U12 = TPS70925DBVR: 150-mA, 30-V, 1-µA IQ Voltage Regulator with Enable, DBV0005A; Alternate PartNumber: TPS70925DBVT; Manufacturer: Texas Instruments; SymbolCreator: Altium; CompType: IC; U/M: EA
U13 = SN6501DBV: Transformer Driver for Isolated Power Supplies, DBV0005A; Alternate Manufacturer: None; Manufacturer: Texas Instruments; SymbolCreator: a0411947; CompType: IC; U/M: EA
U14 = TPS7A3001DGNR: -36V, -200mA, Ultralow-Noise, Negative Linear Regulator; Alternate Manufacturer: None; Manufacturer: Texas Instruments; CompType: IC; SymbolCreator: x0120606

## Sheet Voltage Measurment.SchDoc: Voltage Measurement
size 431 x 279 mm; Date: Not shown in title block; ApprovedBy: Not shown in title block; CheckedBy: Not shown in title block; Author: Not shown in title block; CompanyName: Not shown in title block; Engineer: Not shown in title block; Organization: Not shown in title block; Address1: Not shown in title block; Address2: Not shown in title block; Address3: Not shown in title block; Address4: Not shown in title block; DocumentNumber: 1; Revision: Use project parameter SCH_Rev; SheetNumber: 6; SheetTotal: 8; PageSetup: Record=PageOptions¦CenterHorizontal=True¦CenterVertical=True¦PrintScale=1.00¦XCorrection=1.00¦YCorrection=1.00¦PrintKind=0¦BorderSize=5000000¦LeftOffset=0¦BottomOffset=0¦Orientation=2¦PaperLength=1000¦PaperWidth=1000¦Scale=100¦PaperSource=15¦PrintQuality=600¦MediaType=1¦DitherType=10¦PaperKind=Letter¦PrintScaleMode=1
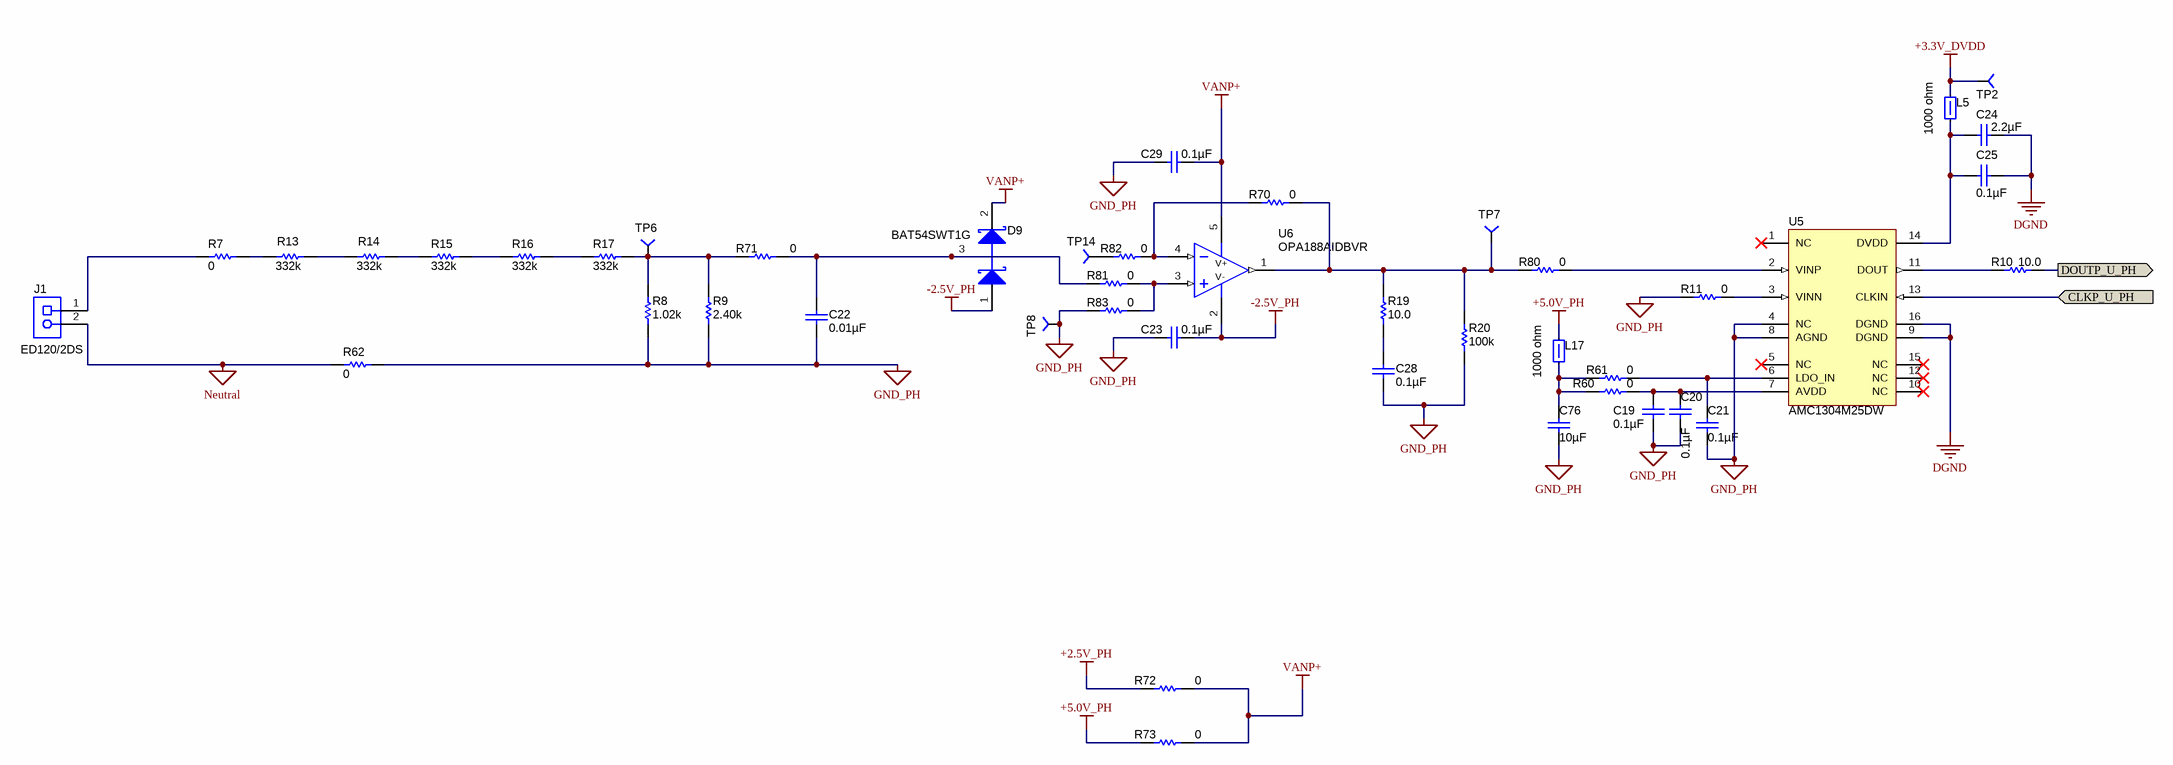
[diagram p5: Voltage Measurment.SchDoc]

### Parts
C19  ValueDisplayed: 0.1µF  [0603]
C20  ValueDisplayed: 0.1µF  [0603]
C21  ValueDisplayed: 0.1µF  [0603]
C22  ValueDisplayed: 0.01µF  [0805_HV]  (hidden comment: GRM2195C1H103JA01D)
C23  ValueDisplayed: 0.1µF  [0603]
C24  ValueDisplayed: 2.2µF  [0603]  (hidden comment: GRM188R71A225KE15D)
C25  ValueDisplayed: 0.1µF  [0603]
C28  ValueDisplayed: 0.1µF  [0603]  (hidden comment: GRM188R72A104KA35D)
C29  ValueDisplayed: 0.1µF  [0603]
C76  ValueDisplayed: 10µF  [1210]
D9  BAT54SWT1G  [SOT-323]
J1  ED120/2DS  [CONN_ED120-2DS]
L5  value 1000 ohm  [MMZ1608_095]  (hidden comment: MMZ1608B102CTA00)
L17  value 1000 ohm  [MMZ1608_095]  (hidden comment: MMZ1608B102CTA00)
R7  ValueDisplayed: 0  [1206]  (hidden comment: RC1206JR-070RL)
R8  ValueDisplayed: 1.02k  [1206]  (hidden comment: RC1206FR-071K02L)
R9  ValueDisplayed: 2.40k  [1206]  (hidden comment: RC1206FR-072K4L)
R10  value 10.0  [0603]
R11  value 0  [0603]
R13  ValueDisplayed: 332k  [1206]  (hidden comment: ERJ-8ENF3323V)
R14  ValueDisplayed: 332k  [1206]  (hidden comment: ERJ-8ENF3323V)
R15  ValueDisplayed: 332k  [1206]  (hidden comment: ERJ-8ENF3323V)
R16  ValueDisplayed: 332k  [1206]  (hidden comment: ERJ-8ENF3323V)
R17  ValueDisplayed: 332k  [1206]  (hidden comment: ERJ-8ENF3323V)
R19  ValueDisplayed: 10.0  [0603]  (hidden comment: RC0603FR-0710RL)
R20  ValueDisplayed: 100k  [0603]  (hidden comment: CRCW0603100KJNEA)
R60  value 0  [0603]
R61  value 0  [0603]
R62  ValueDisplayed: 0  [1206]  (hidden comment: CRCW12060000Z0EA)
R70  value 0  [0603]
R71  value 0  [0603]
R72  value 0  [0603]
R73  value 0  [0603]
R80  value 0  [0603]
R81  value 0  [0603]
R82  value 0  [0603]
R83  value 0  [0603]
TP2  (no value)  [TP-040_RND]
TP6  (no value)  [TP-040_RND]
TP7  (no value)  [TP-040_RND]
TP8  (no value)  [TP-040_RND]
TP14  (no value)  [TP-040_RND]
U5  AMC1304M25DW  [DW0016B_N]
U6  OPA188AIDBVR  [DBV0005A_N]

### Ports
CLKP_U_PH (in), DOUTP_U_PH (out)

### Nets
+2.5V_PH: R72.1
+3.3V_DVDD: L5.2 TP2.1
+5.0V_PH: L17.2 R73.1
-2.5V_PH: C23.2 D9.1(A) U6.2(V-)
DGND: C24.1 C25.1 U5.9(DGND) U5.16(DGND)
GND_PH: C19.2 C20.2 C21.2 C22.1 C23.1 C28.2 C29.1 C76.1 R8.1 R9.1 R11.1 R20.1 R62.2 R83.1 TP8.1 U5.4(NC) U5.8(AGND)
Neutral: J1.2 R62.1
VANP+: C29.2 D9.2(K) R72.2 R73.2 U6.5(V+)
CLKP_U_PH: U5.13(CLKIN) ; port CLKP_U_PH
DOUTP_U_PH: R10.2 ; port DOUTP_U_PH
NetC19_1: C19.1 C20.1 R60.2 U5.7(AVDD)
NetC21_1: C21.1 R61.2 U5.6(LDO_IN)
NetC22_2: C22.2 D9.3(C) R71.2 R81.1
NetC24_2: C24.2 C25.2 L5.1 U5.14(DVDD)
NetC28_1: C28.1 R19.1
NetC76_2: C76.2 L17.1 R60.1 R61.1
NetJ1_1: J1.1 R7.1
NetR7_2: R7.2 R13.1
NetR8_2: R8.2 R9.2 R17.2 R71.1 TP6.1
NetR10_1: R10.1 U5.11(DOUT)
NetR11_2: R11.2 U5.3(VINN)
NetR13_2: R13.2 R14.1
NetR14_2: R14.2 R15.1
NetR15_2: R15.2 R16.1
NetR16_2: R16.2 R17.1
NetR19_2: R19.2 R20.2 R70.2 R80.1 TP7.1 U6.1(OUT)
NetR70_1: R70.1 R82.2 U6.4(IN-)
NetR80_2: R80.2 U5.2(VINP)
NetR81_2: R81.2 R83.2 U6.3(IN+)
NetR82_1: R82.1 TP14.1

Not connected (* = marked no-connect by the designer): U5 1(NC)* 5(NC)* 10(NC)* 12(NC)* 15(NC)*

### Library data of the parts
C19-C21 C23 C29 = C0603C104K5RACTU: as C30 on sheet Current Measurement
C22 = GRM2195C1H103JA01D: CAP, CERM, 0.01 µF, 50 V, +/- 5%, C0G/NP0, 0805; Manufacturer: MuRata; Polarized: N; CompType: Capacitor; Value: 0.01uF; U/M: EA; Cap_F: 0.00000001; Tolerance_%: 5; Value1: Unknown; VDC_V: 50; Value2: 50V; TaMin_C: -55; TaMax_C: 125; Cap_Case: 0805; AEC Category: Q200
C24 = GRM188R71A225KE15D: as C35 on sheet Current Measurement
C25 = 06033C104JAT2A: as C34 on sheet Current Measurement
C28 = GRM188R72A104KA35D: as C32 on sheet Current Measurement
C76 = GMK325AB7106MM-T: as C72 on sheet Current Measurement
D9 = BAT54SWT1G: as D10 on sheet Current Measurement
J1 = ED120/2DS: TERMINAL BLOCK 5.08MM VERT 2POS, TH; Manufacturer: On-Shore Technology; SymbolCreator: a0412235; U/M: EA
L5 L17 = MMZ1608B102CTA00: as L8 on sheet Current Measurement
R7 = RC1206JR-070RL: RES, 0, 5%, 0.25 W, 1206; Manufacturer: Yageo America; CompType: Resistor; Value: 0; Value_Code: 0000; Tolerance_%: 5; Power_W: 0.25; Value2: 0.25W; VDC_V: 200; TempCo: 200 ppm/C; EIA_Code: E24; U/M: EA; AEC Category: Q200
R8 = RC1206FR-072K4L: RES SMD 1.02K OHM 1% 1/4W 1206; Manufacturer: Yageo America; CompType: Resistor; Res_ohm: 2400; Value_Code: 1K02; Tolerance_%: 1; Power_W: 0.25; Value2: 0.25W; VDC_V: 200; TempCo: 100 ppm/C; U/M: EA
R9 = RC1206FR-072K4L: RES, 2.40 k, 1%, 0.25 W, 1206; Manufacturer: Yageo America; CompType: Resistor; Value: 2.40k; Res_ohm: 2400; Value_Code: 2k40; Tolerance_%: 1; Power_W: 0.25; Value2: 0.25W; VDC_V: 200; TempCo: 100 ppm/C; U/M: EA
R10 = CRCW060310R0FKEA: as R33 on sheet Current Measurement
R11 R60 R61 R70-R73 R80-R83 = CRCW06030000Z0EA: as R35 on sheet Current Measurement
R13-R17 = ERJ-8ENF3323V: RES, 332 k, 1%, 0.25 W, 1206; Manufacturer: Panasonic; CompType: Resistor; Value: 332k; Res_ohm: 332000; Tolerance_%: 1; Power_W: 0.25; Value2: 0.25W; VDC_V: 200; TempCo: 100 ppm/C; EIA_Code: E96; U/M: EA
R19 = RC0603FR-0710RL: as R36 on sheet Current Measurement
R20 = CRCW0603100KJNEA: RES, 100 k, 5%, 0.1 W, 0603; Manufacturer: Vishay-Dale; CompType: Resistor; Value: 100k; Res_ohm: 100000; Tolerance_%: 5; Power_W: 0.1; Value2: 0.1W; VDC_V: 75; TempCo: 200 ppm/C; EIA_Code: E24; U/M: EA; AEC Category: Q200
R62 = CRCW12060000Z0EA: as R57 on sheet Current Measurement
TP2 TP6-TP8 TP14 = TP-040_RND: as TP9 on sheet Current Measurement
U5 = AMC1304M25DW: 20 MHz, Isolated Delta-Sigma Modulator, DW0016B; Manufacturer: Texas Instruments; SymbolCreator: a0411947; CompType: IC; U/M: EA
U6 = OPA188AIDBVR: as U10 on sheet Current Measurement

## Sheet Power Supply Voltage Measurement.SchDoc: Voltage Measurement
size 431 x 279 mm; Date: Not shown in title block; ApprovedBy: Not shown in title block; CheckedBy: Not shown in title block; Author: Not shown in title block; CompanyName: Not shown in title block; Engineer: Not shown in title block; Organization: Not shown in title block; Address1: Not shown in title block; Address2: Not shown in title block; Address3: Not shown in title block; Address4: Not shown in title block; DocumentNumber: 1; Revision: Use project parameter SCH_Rev; SheetNumber: 7; SheetTotal: 8; PageSetup: Record=PageOptions¦CenterHorizontal=True¦CenterVertical=True¦PrintScale=1.00¦XCorrection=1.00¦YCorrection=1.00¦PrintKind=0¦BorderSize=5000000¦LeftOffset=0¦BottomOffset=0¦Orientation=2¦PaperLength=1000¦PaperWidth=1000¦Scale=100¦PaperSource=15¦PrintQuality=600¦MediaType=1¦DitherType=10¦PaperKind=Letter¦PrintScaleMode=1
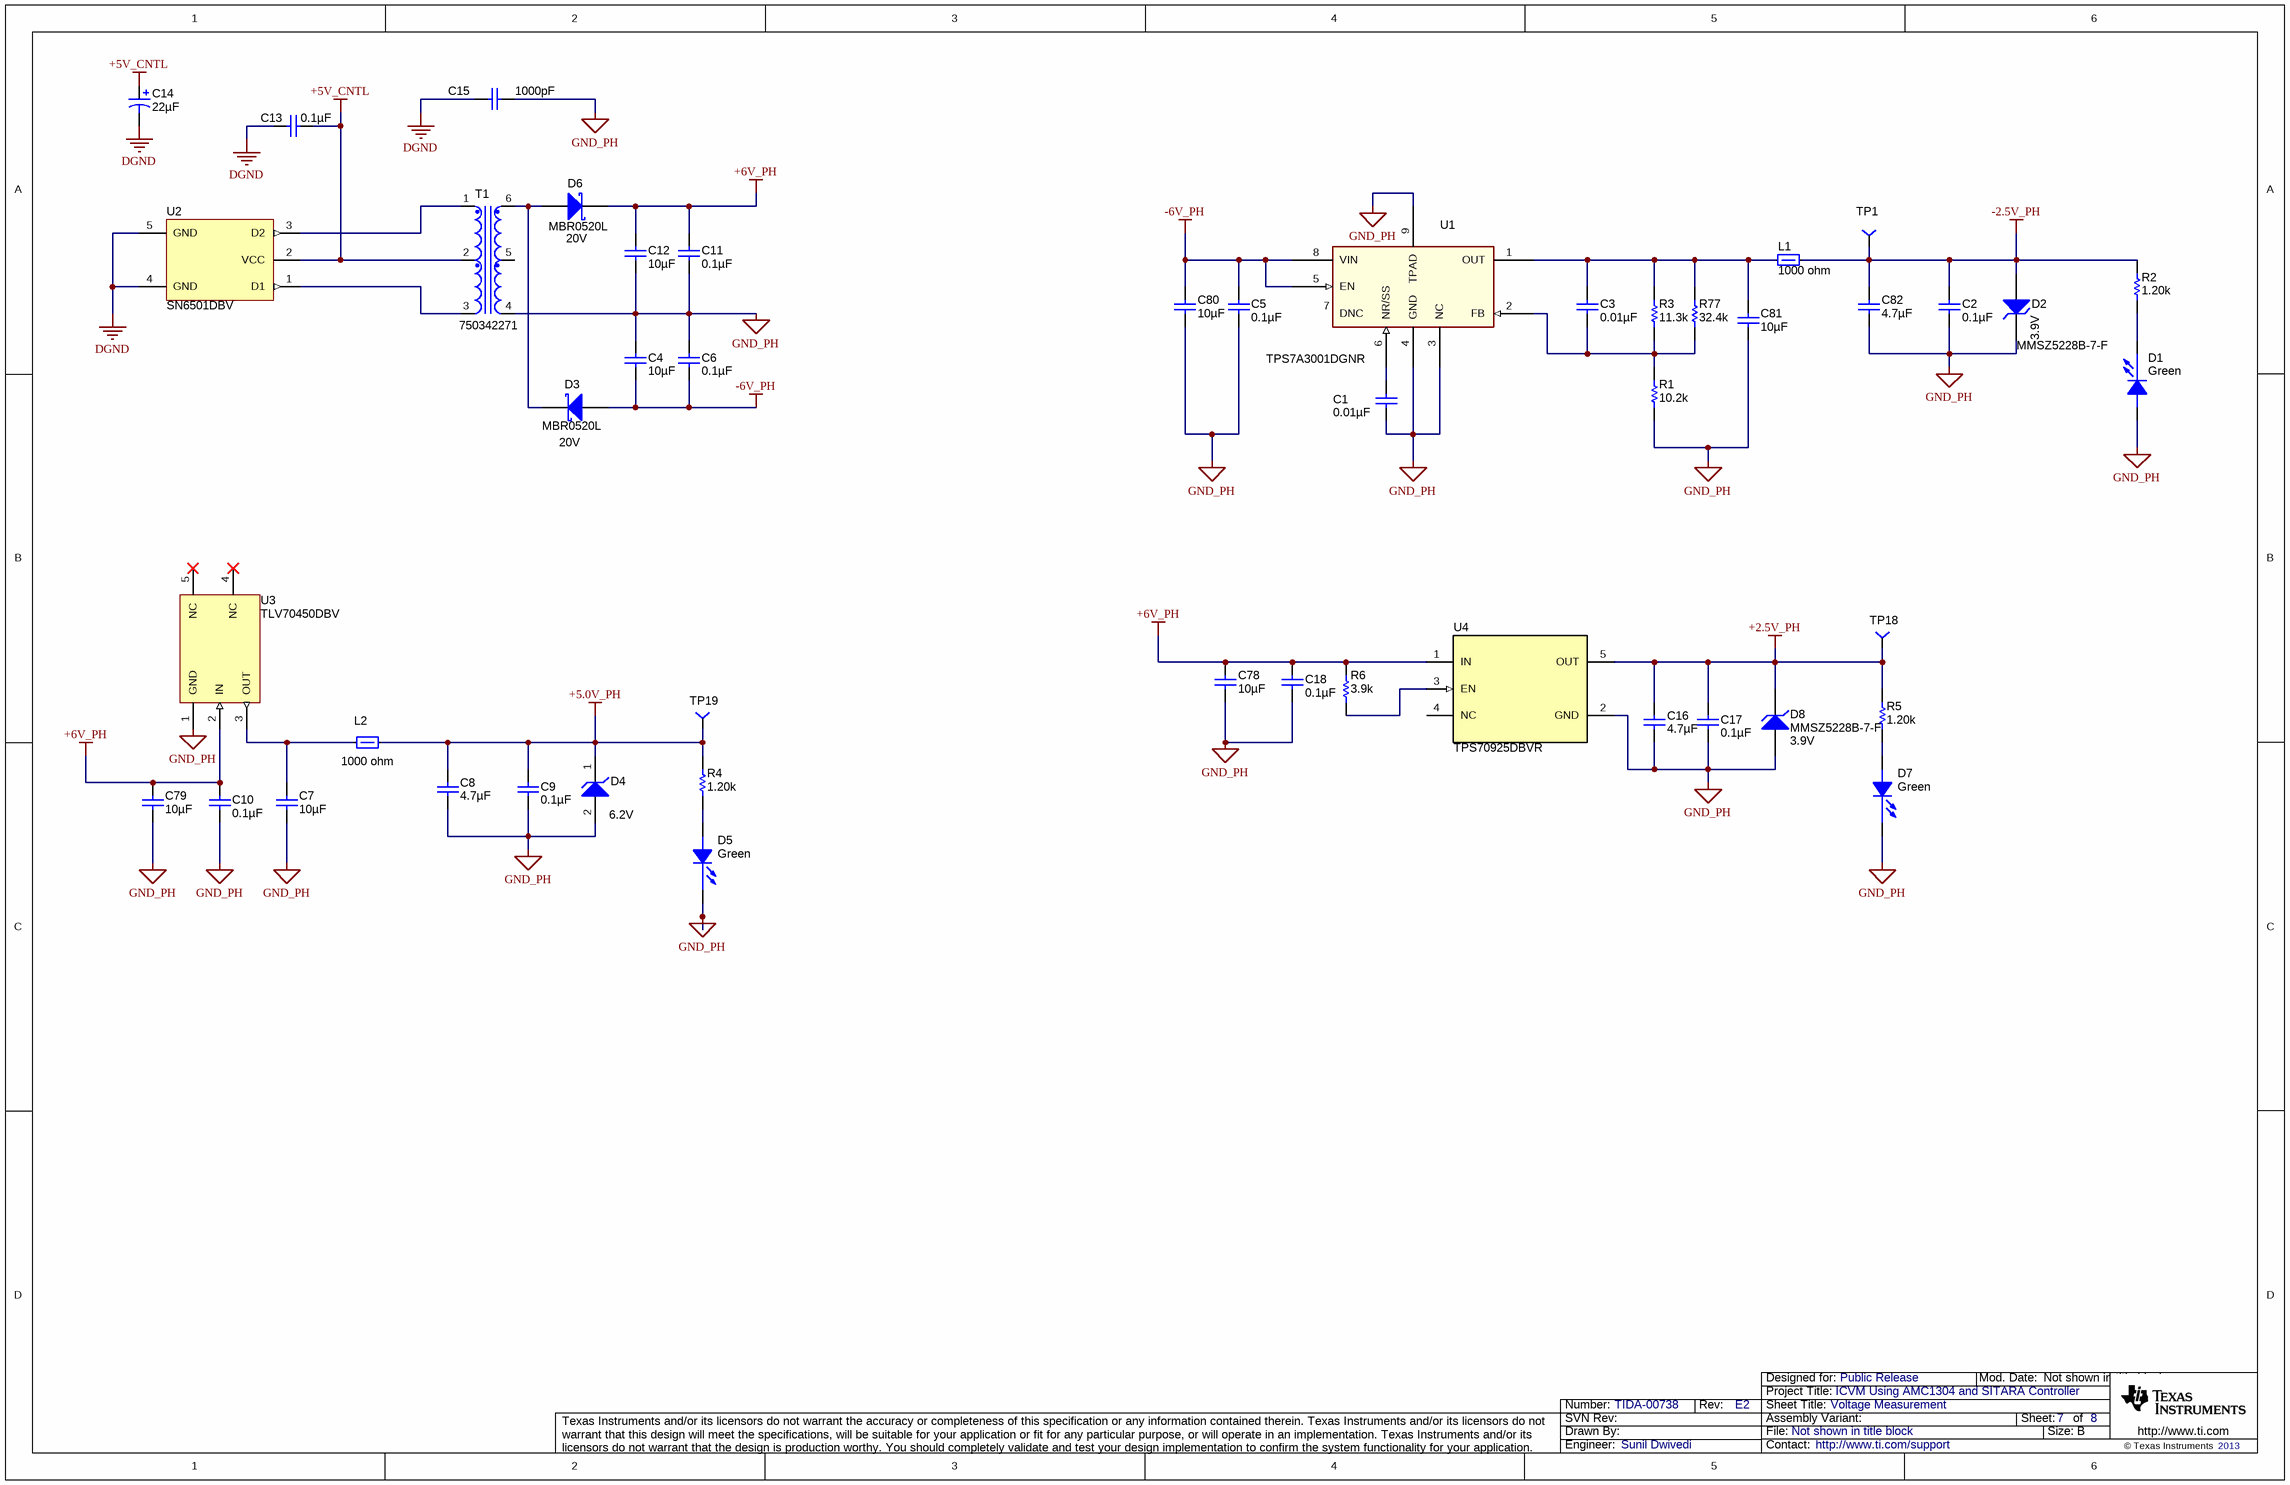
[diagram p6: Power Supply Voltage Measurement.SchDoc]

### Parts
C1  ValueDisplayed: 0.01µF  [0603]
C2  ValueDisplayed: 0.1µF  [0603]
C3  ValueDisplayed: 0.01µF  [0603]
C4  ValueDisplayed: 10µF  [1210]
C5  ValueDisplayed: 0.1µF  [0603]
C6  ValueDisplayed: 0.1µF  [0603]
C7  ValueDisplayed: 10µF  [1210]
C8  ValueDisplayed: 4.7µF  [0805_HV]
C9  ValueDisplayed: 0.1µF  [0603]
C10  ValueDisplayed: 0.1µF  [0603]
C11  ValueDisplayed: 0.1µF  [0603]
C12  ValueDisplayed: 10µF  [1210]
C13  ValueDisplayed: 0.1µF  [0603]
C14  ValueDisplayed: 22µF  [SM_RADIAL_5MM]  (hidden comment: UUD1E220MCL1GS)
C15  value 1000pF  [CAP_200mil]
C16  ValueDisplayed: 4.7µF  [0805_HV]
C17  ValueDisplayed: 0.1µF  [0603]
C18  ValueDisplayed: 0.1µF  [0603]
C78  ValueDisplayed: 10µF  [1210]
C79  ValueDisplayed: 10µF  [1210]
C80  ValueDisplayed: 10µF  [1210]
C81  ValueDisplayed: 10µF  [1210]
C82  ValueDisplayed: 4.7µF  [0805_HV]
D1  value Green  [LED0603AA]
D2  MMSZ5228B-7-F  value 3.9V  [SOD-123]
D3  MBR0520L  value 20V  [SOD-123]
D4  value 6.2V  [powerDI123]
D5  value Green  [LED0603AA]
D6  MBR0520L  value 20V  [SOD-123]
D7  value Green  [LED0603AA]
D8  MMSZ5228B-7-F  value 3.9V  [SOD-123]
L1  value 1000 ohm  [MMZ1608_095]  (hidden comment: MMZ1608B102CTA00)
L2  value 1000 ohm  [MMZ1608_095]  (hidden comment: MMZ1608B102CTA00)
R1  ValueDisplayed: 10.2k  [0603]  (hidden comment: CRCW060310K2FKEA)
R2  ValueDisplayed: 1.20k  [0603]  (hidden comment: RC0603FR-071K2L)
R3  ValueDisplayed: 11.3k  [0603]  (hidden comment: CRCW060311K3FKEA)
R4  ValueDisplayed: 1.20k  [0603]  (hidden comment: RC0603FR-071K2L)
R5  ValueDisplayed: 1.20k  [0603]  (hidden comment: RC0603FR-071K2L)
R6  value 3.9k  [0603]
R77  ValueDisplayed: 32.4k  [0603]  (hidden comment: CRCW060332K4FKEA)
T1  750342271  [760390015]
TP1  (no value)  [TP-040_RND]
TP18  (no value)  [TP-040_RND]
TP19  (no value)  [TP-040_RND]
U1  TPS7A3001DGNR  [DGN0008D_N]
U2  SN6501DBV  [DBV0005A_N]
U3  TLV70450DBV  [DBV0005A_N]
U4  TPS70925DBVR  [DBV0005A_N]

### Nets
+2.5V_PH: C16.2 C17.1 D8.1(K) R5.2 TP18.1 U4.5(OUT)
+5.0V_PH: C8.2 C9.1 D4.1(K) L2.2 R4.2 TP19.1
+5V_CNTL: C13.2 C14.1(+) T1.2 U2.2(VCC)
+6V_PH: C10.1 C11.1 C12.1 C18.1 C78.2 C79.2 D6.1(K) R6.2 U3.2(IN) U4.1(IN)
-2.5V_PH: C2.1 C82.2 D2.2(A) L1.2 R2.2 TP1.1
-6V_PH: C4.2 C5.1 C6.2 C80.2 D3.2(A) U1.5(EN) U1.8(VIN)
DGND: C13.1 C14.2(-) C15.1 U2.4(GND) U2.5(GND)
GND_PH: C1.1 C2.2 C4.1 C5.2 C6.1 C7.1 C8.1 C9.2 C10.2 C11.2 C12.2 C15.2 C16.1 C17.2 C18.2 C78.1 C79.1 C80.1 C81.1 C82.1 D1.2(A) D2.1(K) D4.2(A) D5.1(C) D7.1(C) D8.2(A) R1.1 T1.4 U1.3(NC) U1.4(GND) U1.9(TPAD) U3.1(GND) U4.2(GND)
NetC1_2: C1.2 U1.6(NR/SS)
NetC3_1: C3.1 R1.2 R3.1 R77.1 U1.2(FB)
NetC3_2: C3.2 C81.2 L1.1 R3.2 R77.2 U1.1(OUT)
NetC7_2: C7.2 L2.1 U3.3(OUT)
NetD1_1: D1.1(C) R2.1
NetD3_1: D3.1(K) D6.2(A) T1.6
NetD5_2: D5.2(A) R4.1
NetD7_2: D7.2(A) R5.1
NetR6_1: R6.1 U4.3(EN)
NetT1_1: T1.1 U2.3(D2)
NetT1_3: T1.3 U2.1(D1)

Not connected (* = marked no-connect by the designer): T1 5; U1 7(DNC); U3 4(NC)* 5(NC)*; U4 4(NC)

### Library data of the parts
C1 C3 = 06031C103JAT2A: as C61 on sheet Power Supply Current Measurment
C2 C5 C6 C9-C11 C13 C17 C18 = C0603C104K5RACTU: as C30 on sheet Current Measurement
C4 C7 C12 C78-C81 = GMK325AB7106MM-T: as C72 on sheet Current Measurement
C8 C16 C82 = C2012X5R1H475K125AB: as C50 on sheet Power Supply Current Measurment
C14 = UUD1E220MCL1GS: as C58 on sheet Power Supply Current Measurment
C15 = 202R18W102KV4E: as C59 on sheet Power Supply Current Measurment
D1 D5 D7 = LED_LG L29K-G2J1-24-Z: as D13 on sheet Power Supply Current Measurment
D2 D8 = MMSZ5228B-7-F: as D15 on sheet Power Supply Current Measurment
D3 D6 = MBR0520LT1G: as D16 on sheet Power Supply Current Measurment
D4 = DFLZ6V2-7: as D12 on sheet Power Supply Current Measurment
L1 L2 = MMZ1608B102CTA00: as L8 on sheet Current Measurement
R1 = CRCW060310K2FKEA: as R50 on sheet Power Supply Current Measurment
R2 R4 R5 = RC0603FR-071K2L: as R52 on sheet Power Supply Current Measurment
R3 = CRCW060311K3FKEA: as R51 on sheet Power Supply Current Measurment
R6 = CRCW06033K90JNEA: as R49 on sheet Power Supply Current Measurment
R77 = CRCW060332K4FKEA: as R69 on sheet Power Supply Current Measurment
T1 = TRNSFMR: as T2 on sheet Power Supply Current Measurment
TP1 TP18 TP19 = TP-040_RND: as TP9 on sheet Current Measurement
U1 = TPS7A3001DGNR: as U14 on sheet Power Supply Current Measurment
U2 = SN6501DBV: as U13 on sheet Power Supply Current Measurment
U3 = TLV70450DBV: as U11 on sheet Power Supply Current Measurment
U4 = TPS70925DBVR: as U12 on sheet Power Supply Current Measurment

## Sheet Hardware_ANSI-B.SchDoc: Hardware_ANSI-B
size 431 x 279 mm; Date: Not shown in title block; ApprovedBy: Not shown in title block; CheckedBy: Not shown in title block; Author: Not shown in title block; CompanyName: Not shown in title block; Engineer: Not shown in title block; Organization: Not shown in title block; Address1: Not shown in title block; Address2: Not shown in title block; Address3: Not shown in title block; Address4: Not shown in title block; DocumentNumber: 1; Revision: Use project parameter SCH_Rev; SheetNumber: 8; SheetTotal: 8; PageSetup: Record=PageOptions¦CenterHorizontal=True¦CenterVertical=True¦PrintScale=1.00¦XCorrection=1.00¦YCorrection=1.00¦PrintKind=0¦BorderSize=5000000¦LeftOffset=0¦BottomOffset=0¦Orientation=2¦PaperLength=1000¦PaperWidth=1000¦Scale=100¦PaperSource=15¦PrintQuality=600¦MediaType=1¦DitherType=10¦PaperKind=Letter¦PrintScaleMode=1
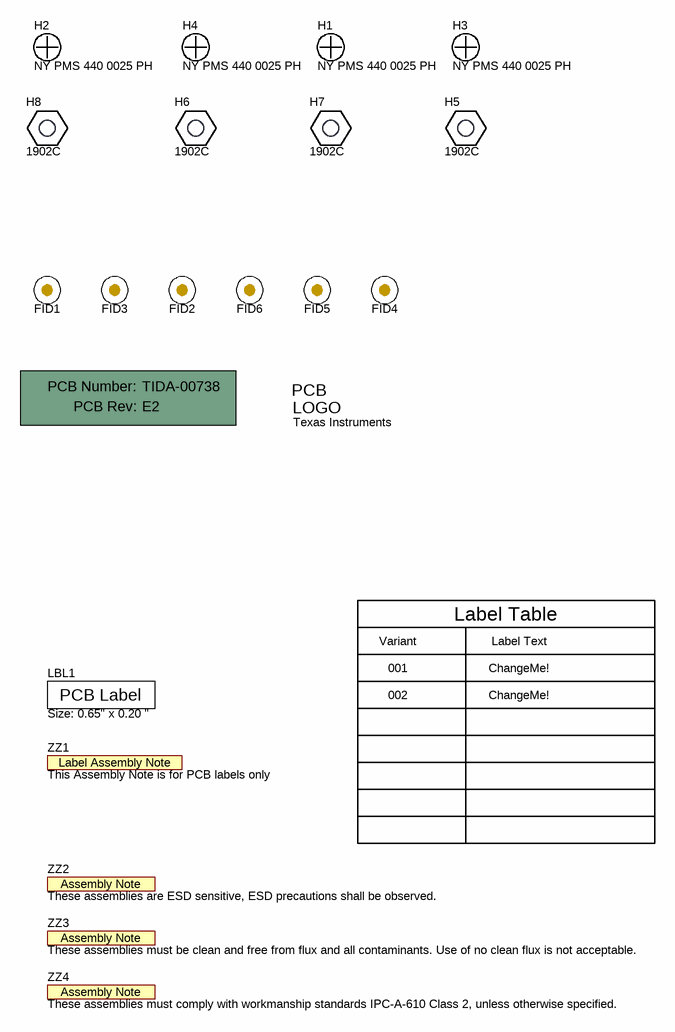
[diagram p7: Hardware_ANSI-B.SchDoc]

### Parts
!PCB  Printed Circuit Board  (value not drawn)  (mechanical)
FID1  Fiducial  [Fiducial10-20]  (value not drawn)
FID2  Fiducial  [Fiducial10-20]  (value not drawn)
FID3  Fiducial  [Fiducial10-20]  (value not drawn)
FID4  Fiducial  [Fiducial10-20]  (value not drawn)
FID5  Fiducial  [Fiducial10-20]  (value not drawn)
FID6  Fiducial  [Fiducial10-20]  (value not drawn)
H1  NY PMS 440 0025 PH  [NY PMS 440 0025 PH]
H2  NY PMS 440 0025 PH  [NY PMS 440 0025 PH]
H3  NY PMS 440 0025 PH  [NY PMS 440 0025 PH]
H4  NY PMS 440 0025 PH  [NY PMS 440 0025 PH]
H5  1902C  [Keystone_1902C]
H6  1902C  [Keystone_1902C]
H7  1902C  [Keystone_1902C]
H8  1902C  [Keystone_1902C]
LBL1  Size: 0.65" x 0.20 "  [Label_650x200]
Logo1  Texas Instruments  [TI_Stacked_Overlay_Small]  (no BOM)
ZZ1  This Assembly Note is for PCB labels only  [AssemblyNoteLabel]  (no BOM)
ZZ2  These assemblies are ESD sensitive, ESD precautions shall be observed.  [AssemblyNote]  (no BOM)
ZZ3  These assemblies must be clean and free from flux and all contaminants. Use of no clean flux is not acceptable.  [AssemblyNote]  (no BOM)
ZZ4  These assemblies must comply with workmanship standards IPC-A-610 Class 2, unless otherwise specified.  [AssemblyNote]  (no BOM)

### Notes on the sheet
- Variant
- Label Table
- Label Text
- 001
- 002
- ChangeMe!

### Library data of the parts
!PCB = PCB: Manufacturer: Any; PartNumber: TIDA-00738; SymbolCreator: a0412235
FID1-FID6 = Fiducial: Fiducial mark.  There is nothing to buy or mount.; SymbolCreator: codlsc
H1-H4 = NY PMS 440 0025 PH: Machine Screw, Round, #4-40 x 1/4, Nylon, Philips panhead; Manufacturer: B&F Fastener Supply; CompType: Hardware; SymbolCreator: codlsc; U/M: EA
H5-H8 = 1902C: Standoff, Hex, 0.5"L #4-40 Nylon; Manufacturer: Keystone; CompType: Hardware
LBL1 = THT-14-423-10: Thermal Transfer Printable Labels, 0.650" W x 0.200" H - 10,000 per roll; Manufacturer: Brady; SymbolCreator: a0412235; CompType: Label
Logo1 = TI_Logo: Texas Instrument Corporate Signature; SymbolCreator: codlsc
ZZ1 = AssemblyNoteLabel: SymbolCreator: a0412235
ZZ2-ZZ4 = AssemblyNote: SymbolCreator: codlsc

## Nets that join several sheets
+2.5V_PH: Voltage Measurment (R72.1), Power Supply Voltage Measurement (6 pins)
+2.5V_USH: Current Measurement (R75.1), Power Supply Current Measurment (6 pins)
+3.3V_DVDD: Current Measurement (L9.2 L14.2), Clock Generator (5 pins), Voltage Measurment (L5.2 TP2.1)
+5.0V_PH: Voltage Measurment (L17.2 R73.1), Power Supply Voltage Measurement (6 pins)
+5.0V_USH: Current Measurement (L8.2 L11.2 R76.1), Power Supply Current Measurment (6 pins)
+5V_CNTL: Clock Generator (J2.2 J3.3), Power Supply Current Measurment (C57.2 C58.1 T2.2 U13.2), Power Supply Voltage Measurement (C13.2 C14.1 T1.2 U2.2)
-2.5V_PH: Voltage Measurment (C23.2 D9.1 U6.2), Power Supply Voltage Measurement (6 pins)
-2.5V_USH: Current Measurement (R78.1), Power Supply Current Measurment (6 pins)
DGND: Current Measurement (8 pins), Clock Generator (11 pins), Power Supply Current Measurment (5 pins), Voltage Measurment (C24.1 C25.1 U5.9 U5.16), Power Supply Voltage Measurement (5 pins)
GND_PH: Voltage Measurment (17 pins), Power Supply Voltage Measurement (33 pins)
GND_USH: Current Measurement (27 pins), Power Supply Current Measurment (33 pins)
CLKP_CH_U: Current Measurement (U9.13), Clock Generator (R29.1)
CLKP_CH_V: Current Measurement (U8.13), Clock Generator (R25.1)
CLKP_U_PH: Clock Generator (R22.1), Voltage Measurment (U5.13)
DOUTP_CH_U: Current Measurement (R41.2), Clock Generator (R31.1)
DOUTP_CH_V: Current Measurement (R33.2), Clock Generator (R28.1)
DOUTP_U_PH: Clock Generator (R23.1), Voltage Measurment (R10.2)

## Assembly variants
001: not fitted C15 C22 C28 C32 C40 C46 C59 FID1 FID2 FID3 FID4 FID5 FID6 R9 R19 R20 R35 R36 R43 R48 R57 R60 R63 R64 R66 R67 R69 R73 R76 R77 R79 R82 R83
